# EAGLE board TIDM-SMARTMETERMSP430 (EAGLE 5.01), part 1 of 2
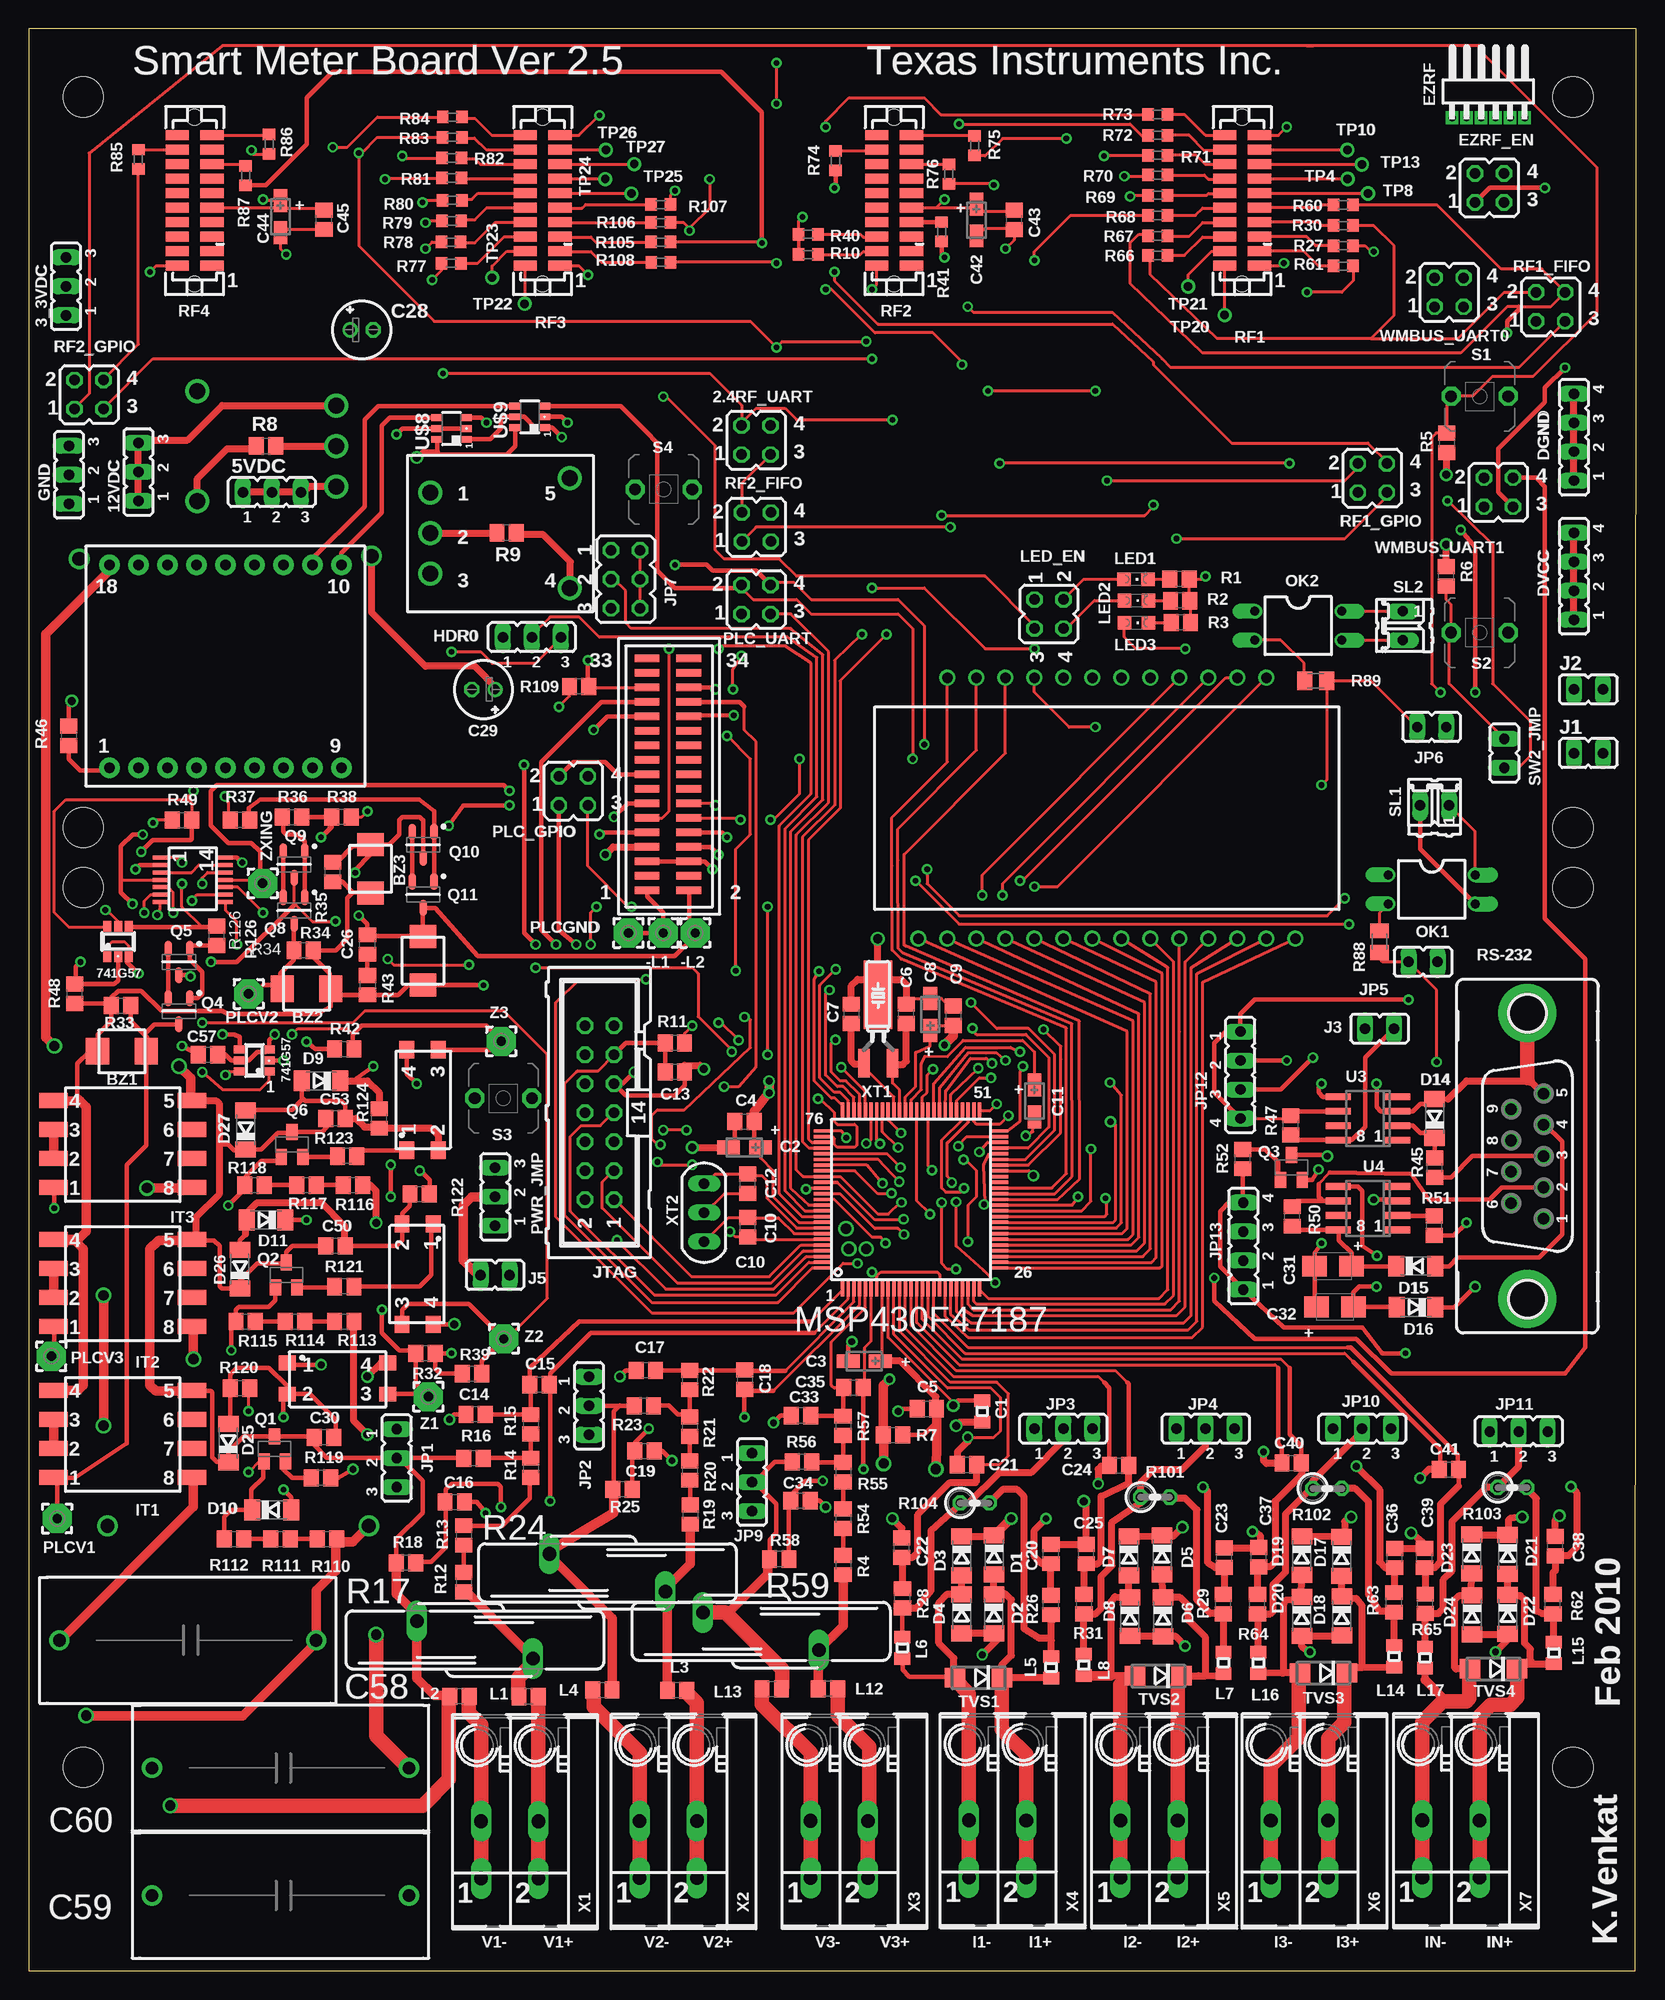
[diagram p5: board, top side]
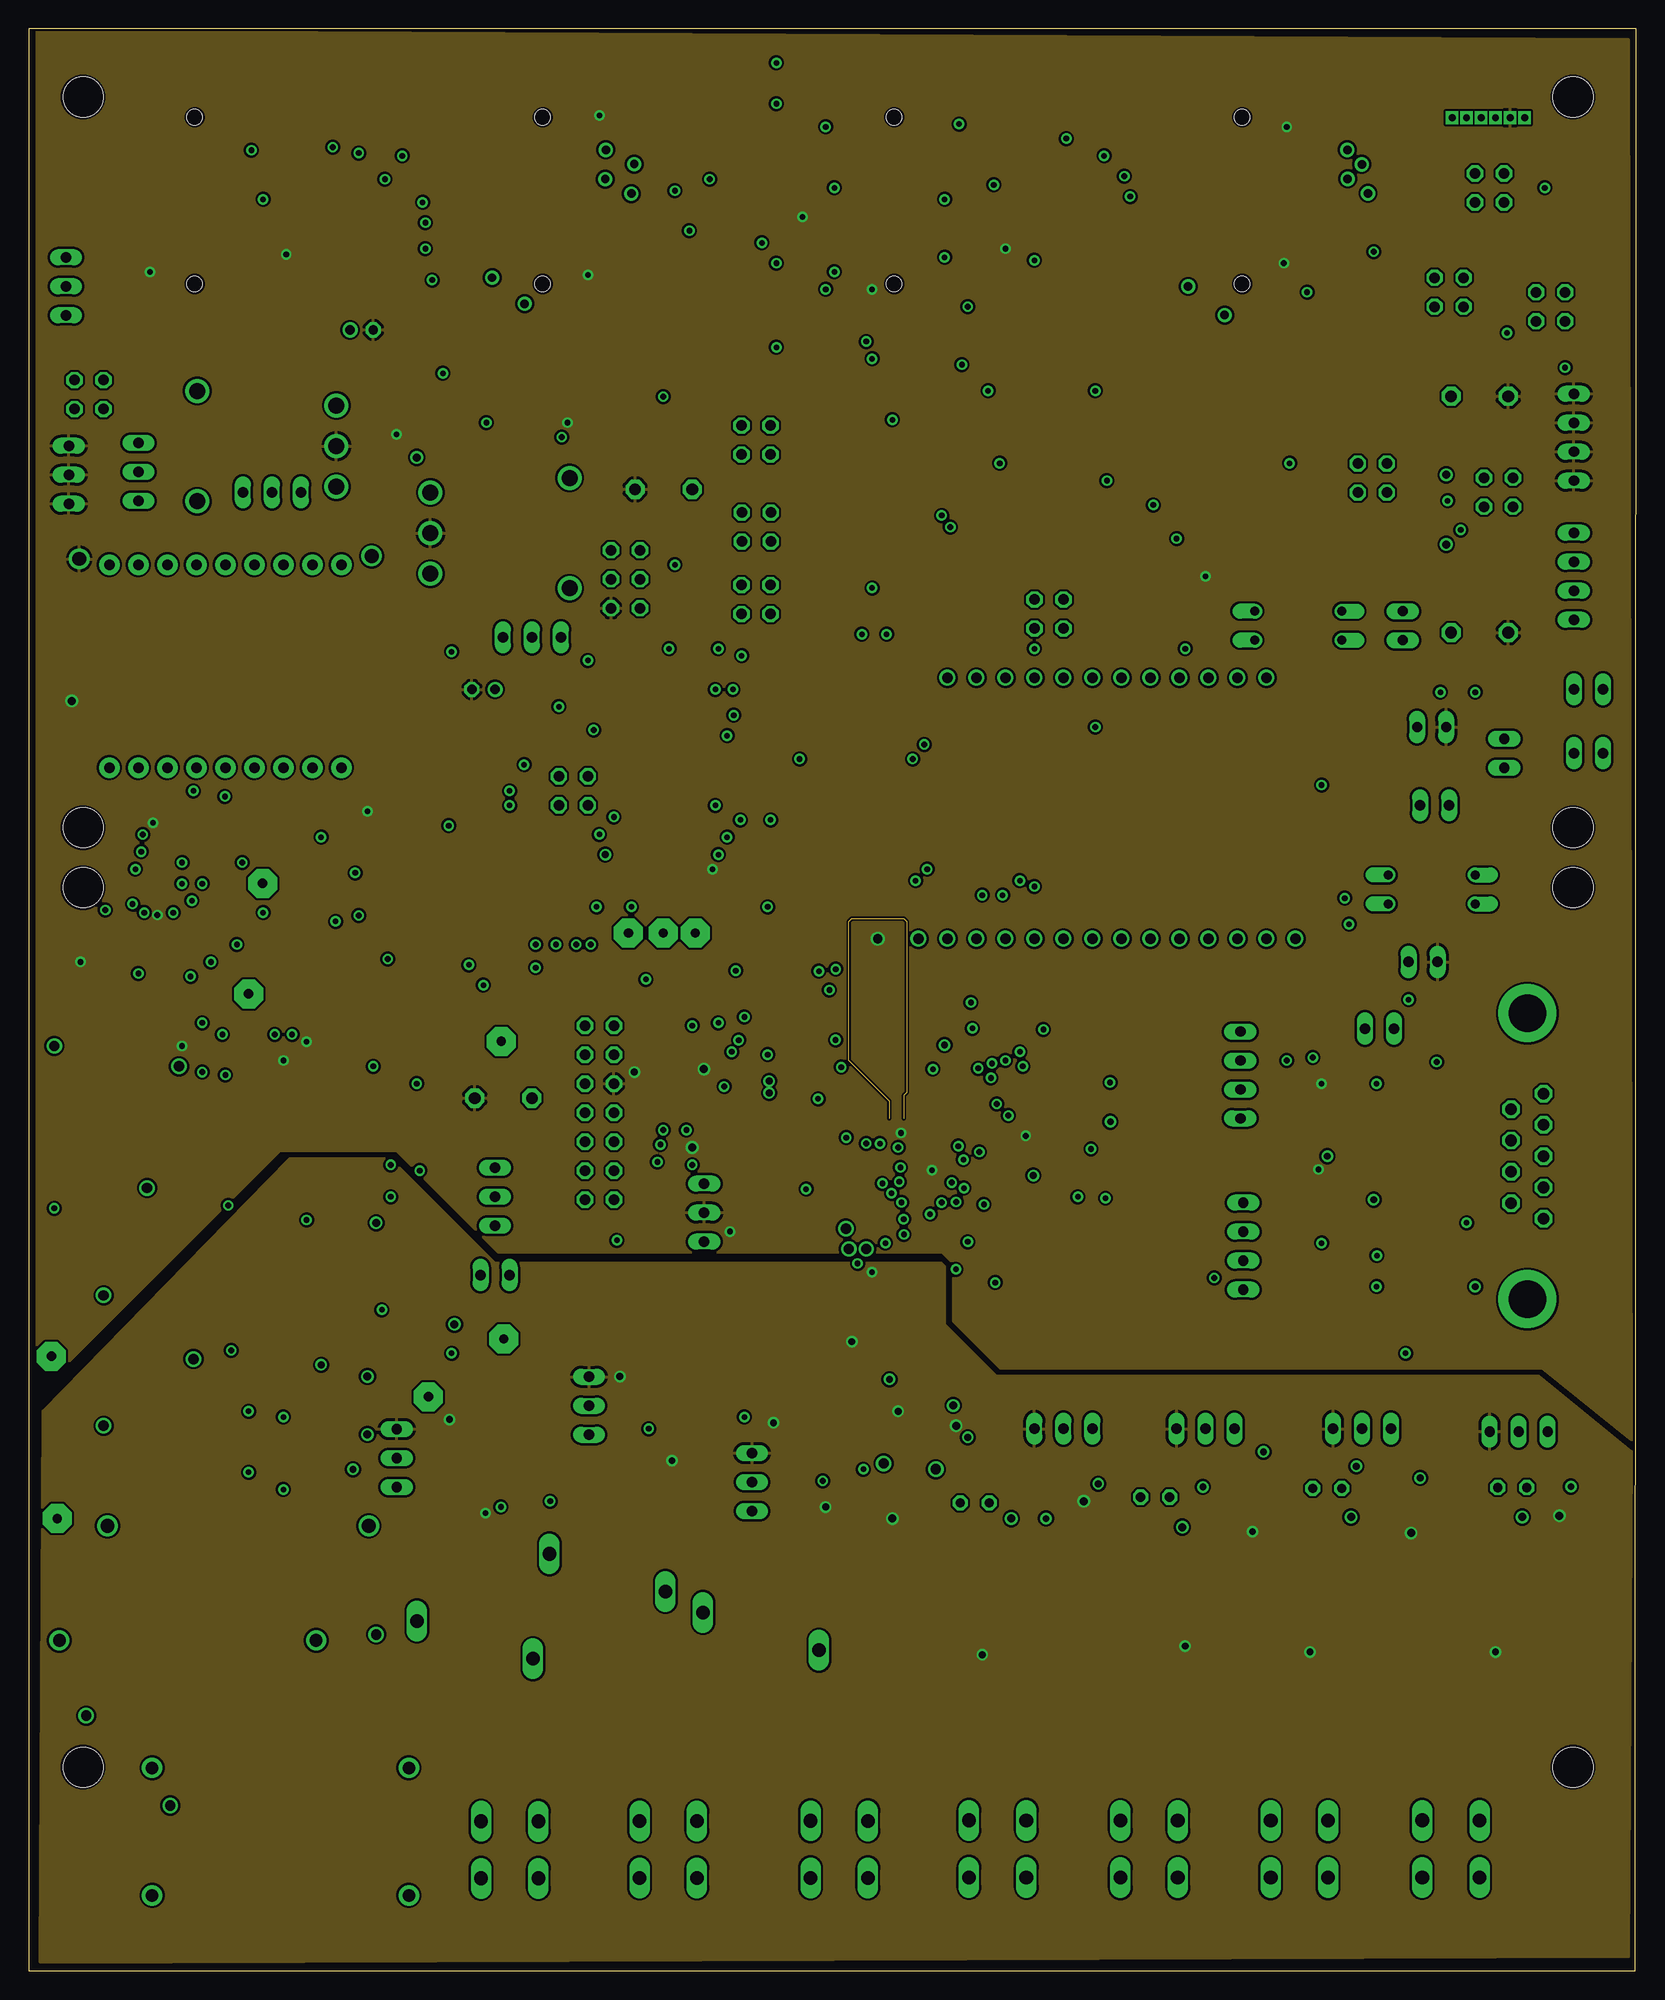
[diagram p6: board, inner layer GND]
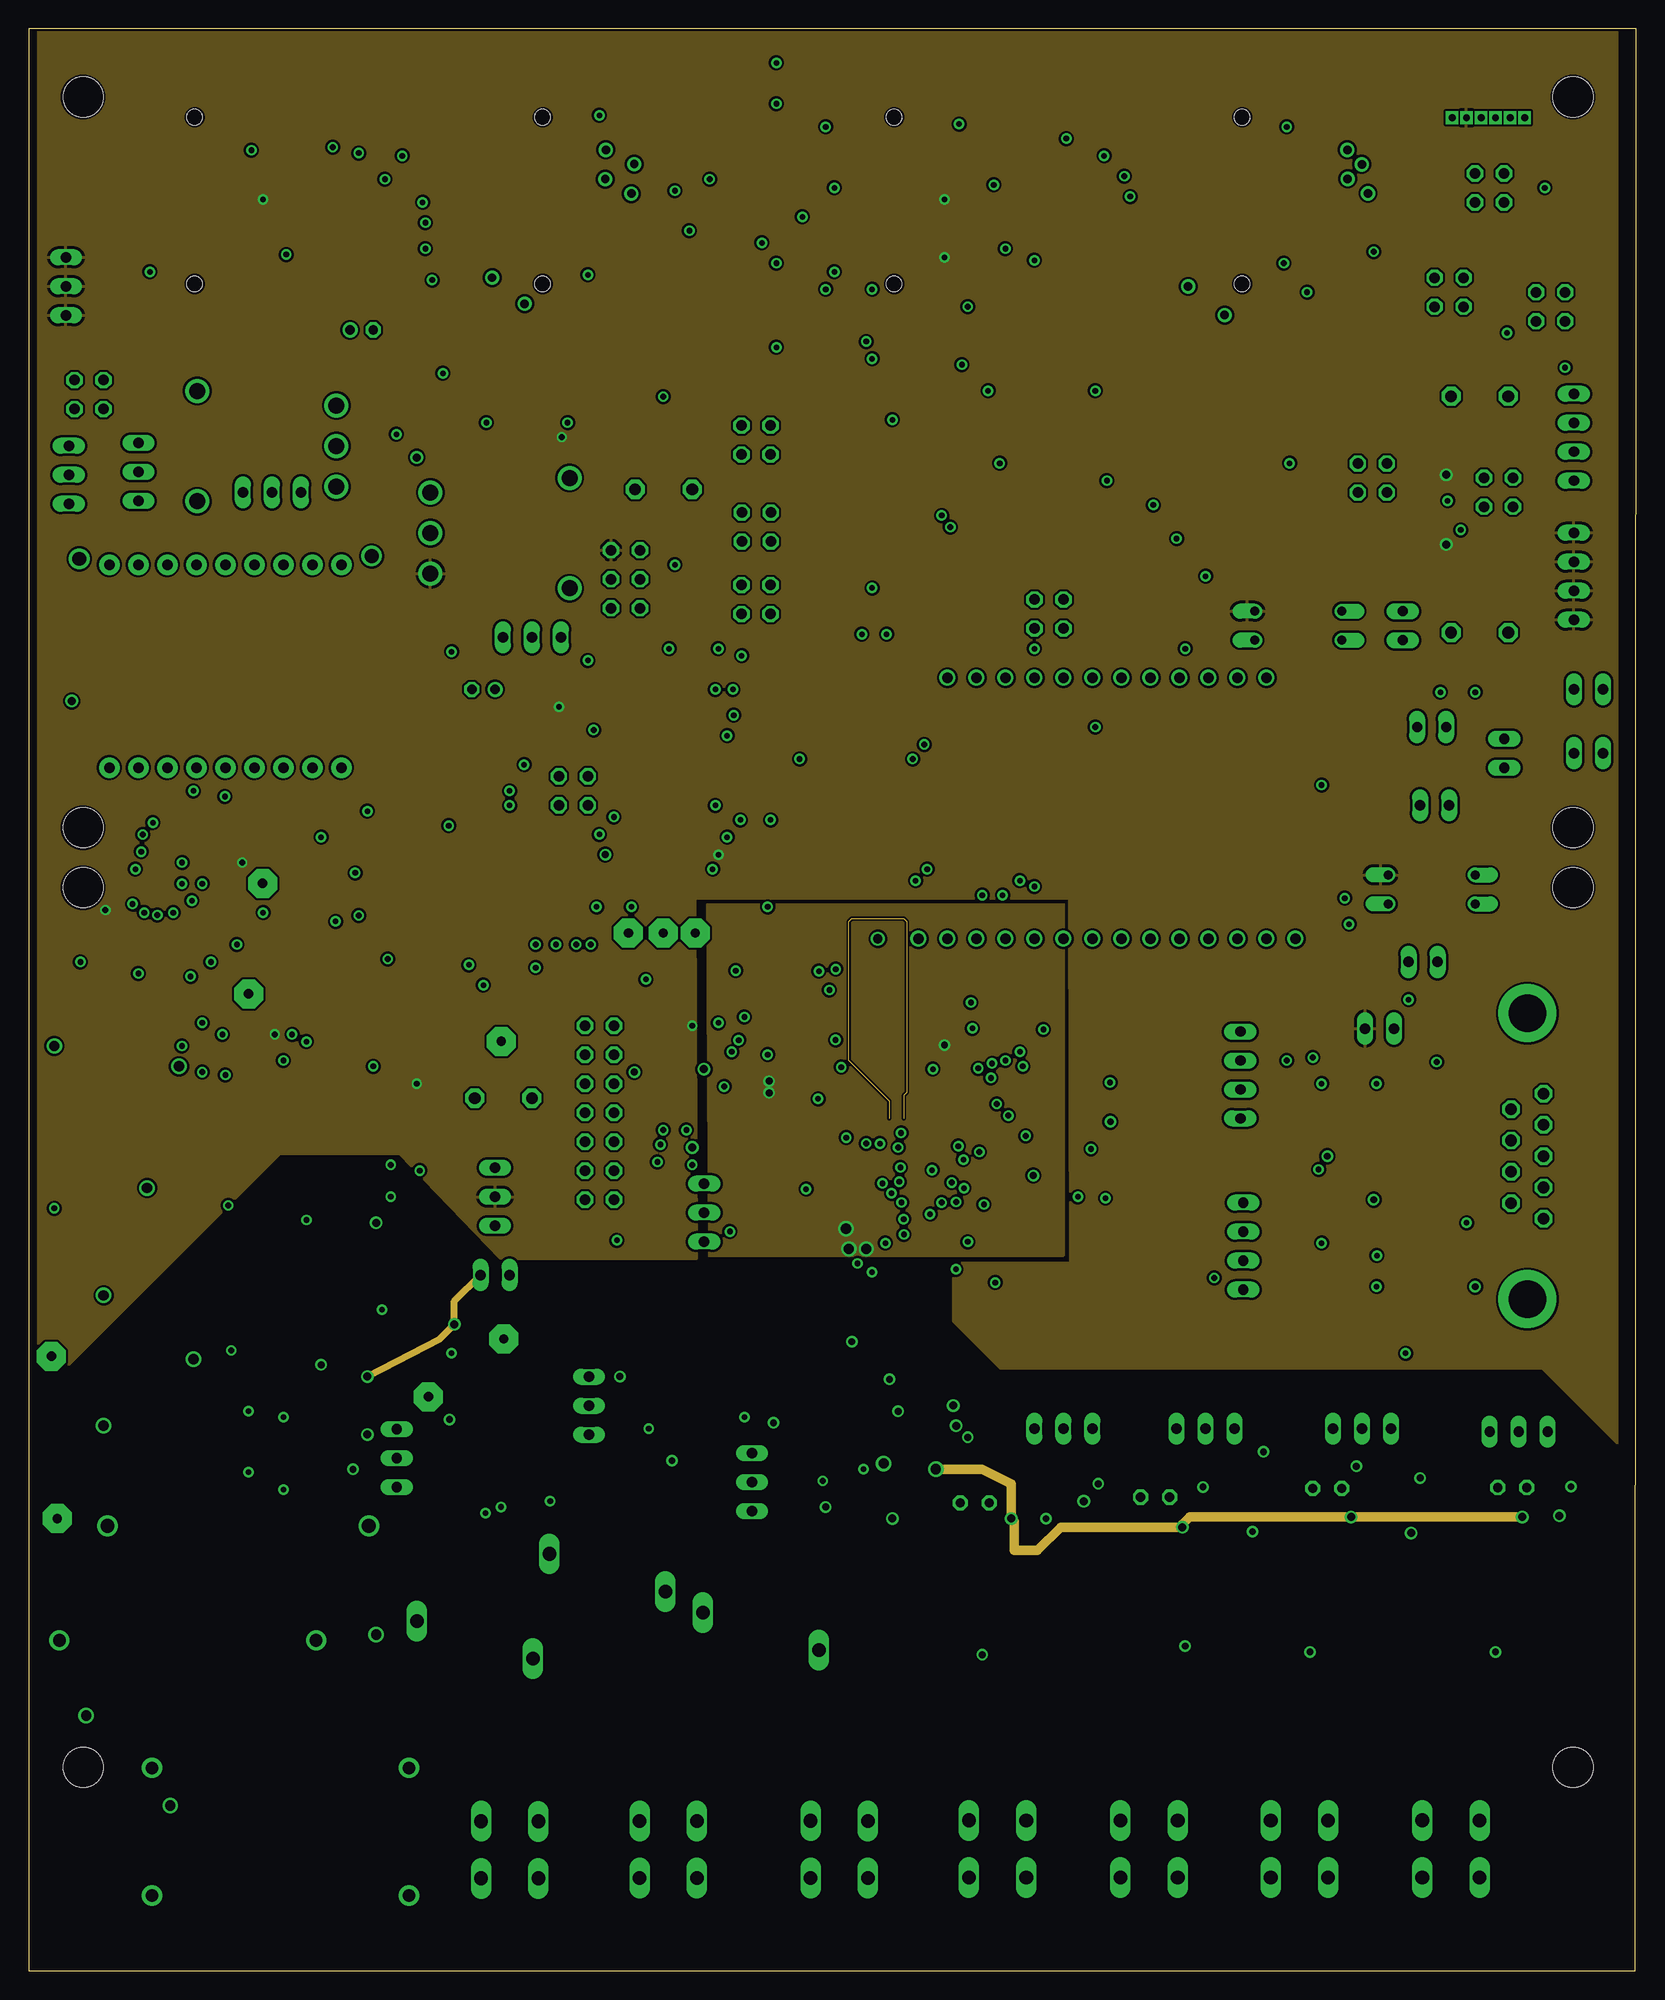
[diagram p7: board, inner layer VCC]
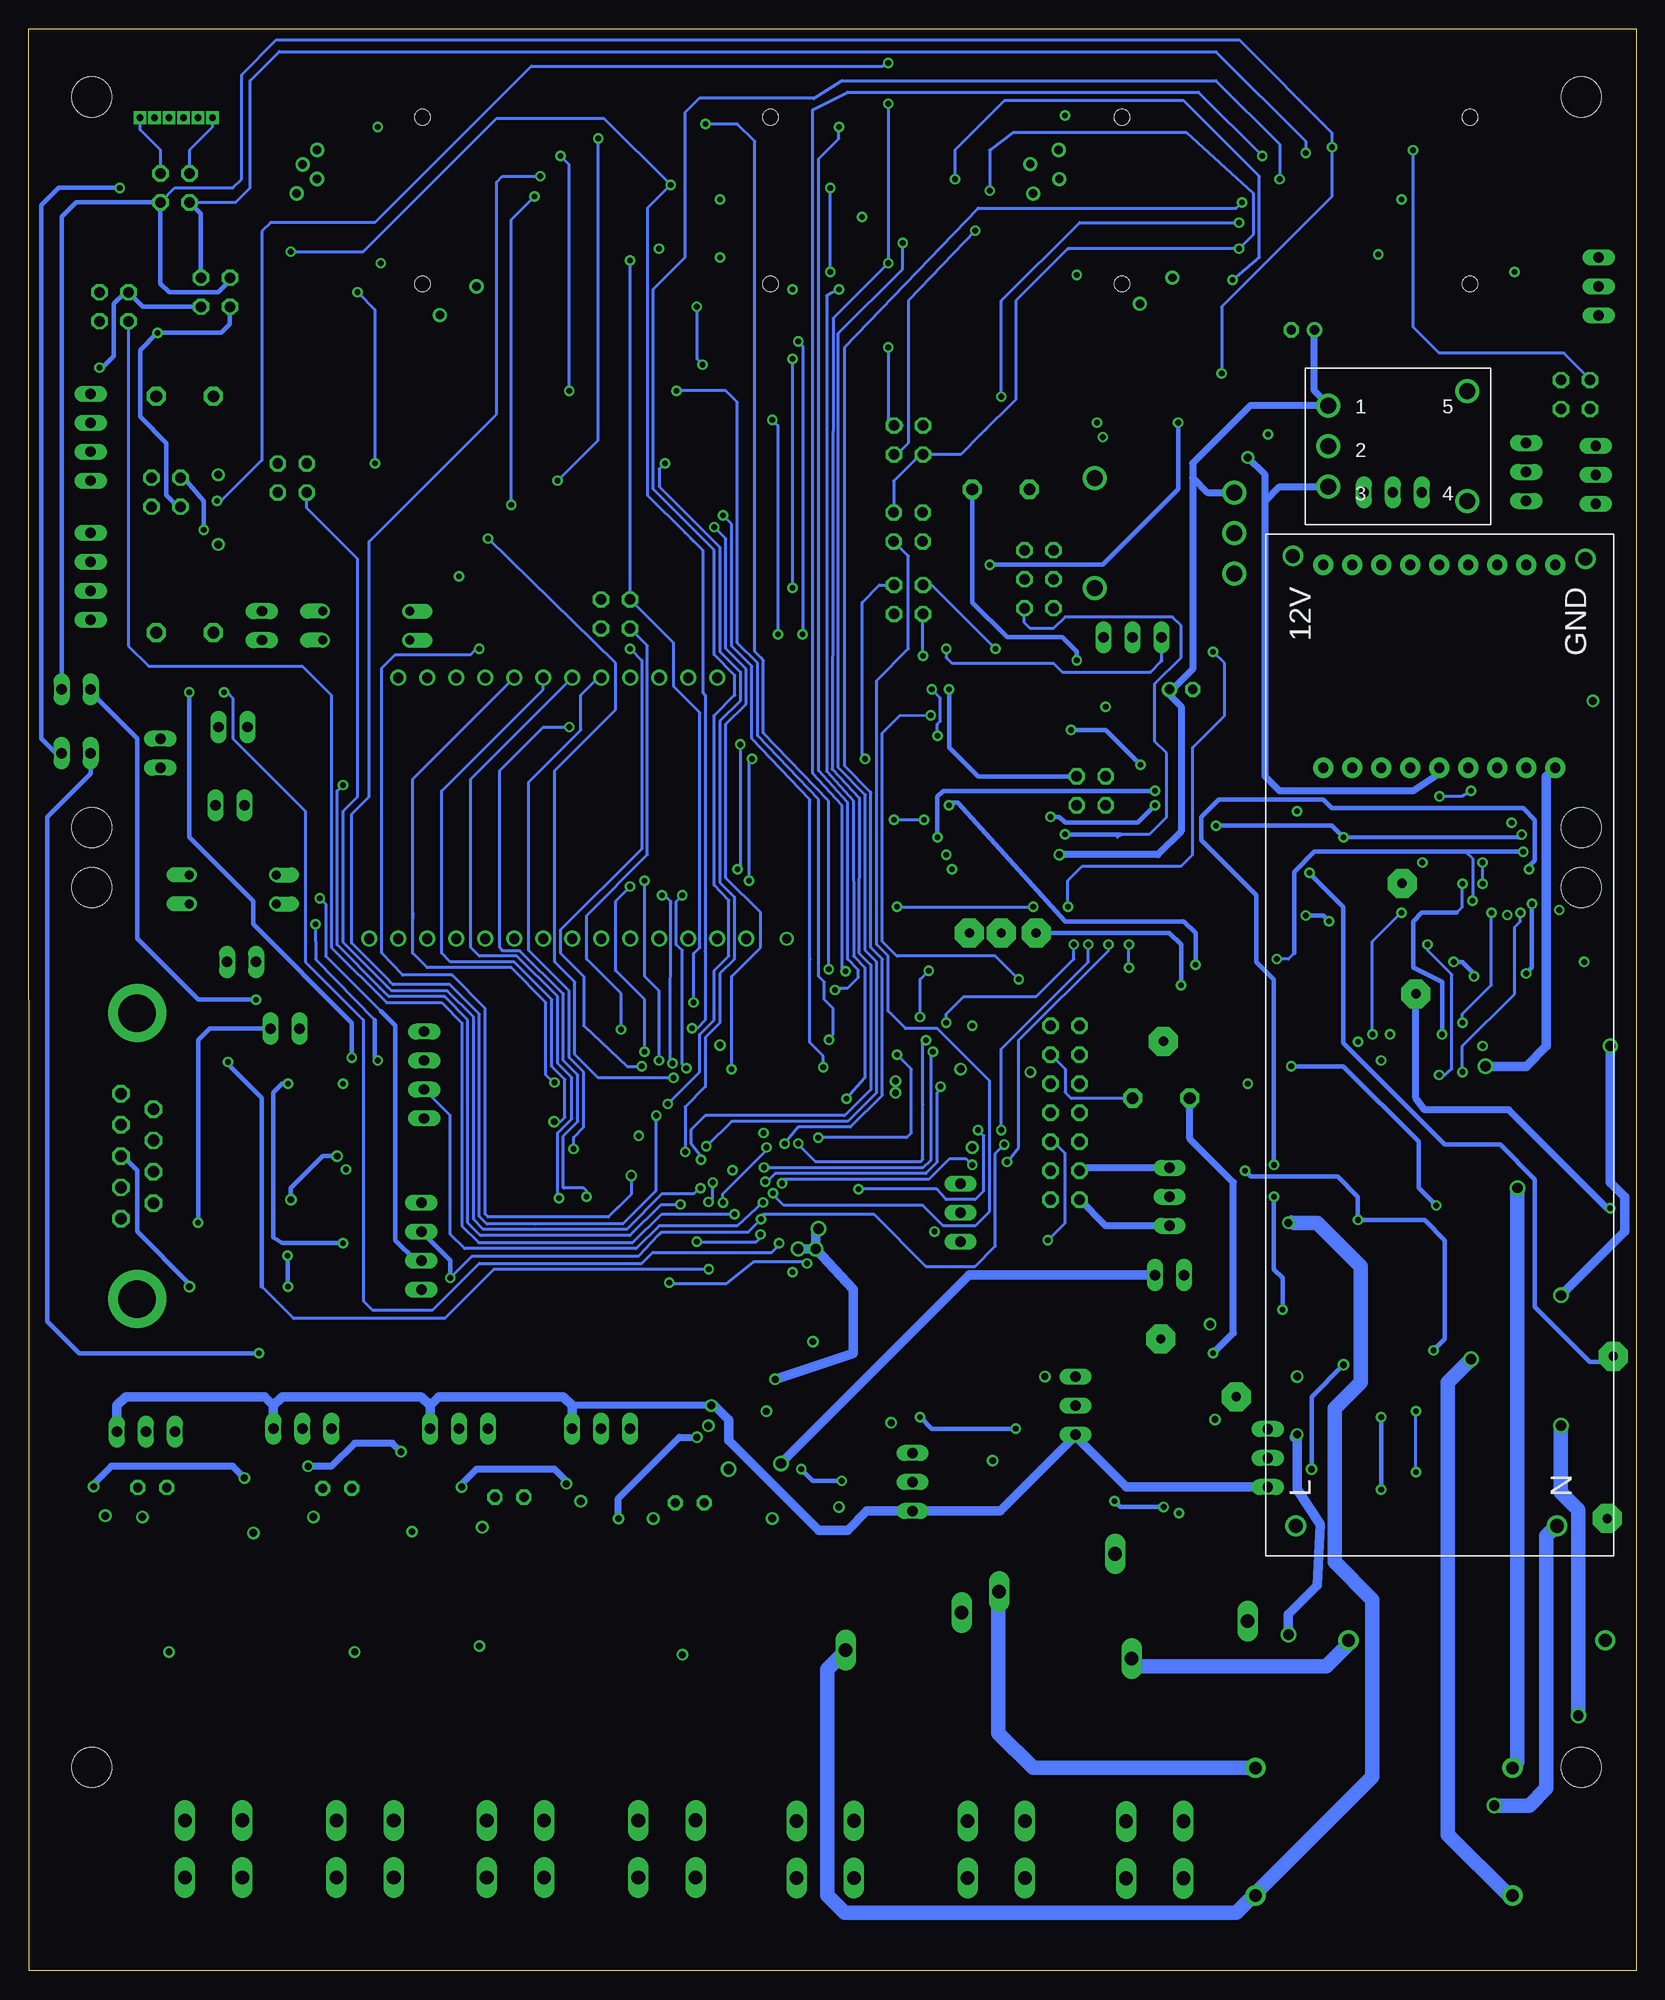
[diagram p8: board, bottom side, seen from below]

Size 140.8 x 170.18 mm. Coordinates in mm from the lower left corner, seen from the top.
Outline: 0,0 140.75,0 140.8,170.18 0,170.18 0,0
Copper layers (1*2*15*16): Top 0.035mm / dielectric 1.5mm / GND 0.035mm / dielectric 1.5mm / VCC 0.035mm / dielectric 1.5mm / Bottom 0.035mm
Design rules "MSP430 PCBExpress ZA 06 *": minimum track width 8mil, minimum drill 14mil, track to track 8mil, track to pad 8mil, pad to pad 7mil, via to via 10mil, smd to smd 8mil, copper to edge 8mil, drill to drill 8mil, minimum pad ring 10mil, minimum via ring 8mil, stop-mask expansion 8mil, vias tented up to drill 15mil, thermal gap 10mil
Holes 3.5 mm at 4.78,100.16 4.78,94.91 4.78,17.85 135.28,164.18 135.28,100.16 135.28,94.91 135.28,17.85 4.78,164.18

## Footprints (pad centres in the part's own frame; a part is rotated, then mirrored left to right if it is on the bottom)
JP2Q = drill 0.914 octagon: 1 -1.27,-1.27; 2 -1.27,1.27; 3 1.27,-1.27; 4 1.27,1.27
JP2 = drill 0.914 long: 1 -2.54,0; 2 0,0; 3 2.54,0
SOT23-6 = smd 0.69 x 0.99: 1 -0.95,-1.29; 2 0,-1.29; 3 0.95,-1.29; 4 0.95,1.3; 5 0.006,1.3; 6 -0.95,1.3
2,54/0,8 = drill 0.813 pad 2.54 octagon: 1 0,0
SOD15 = smd 2.028 x 2.3: P$1 -2.24,0.03; P$2 2.03,0.03
0805 = smd 1.092 x 1.397: 1 -0.94,0; 2 0.94,0
CT3216 = smd 2 x 1.2: + -1.4,0; - 1.4,0
C0805 = smd 1.3 x 1.5: 1 -0.85,0; 2 0.85,0
E2-5 = drill 0.813 pad 1.27 round: + -1.016,0 | drill 0.813 pad 1.27 octagon: - 1.016,0
B/3528-21W = smd 2.15 x 1.8: + 1.625,0; - -1.625,0
C17 = drill 1.1 pad 1.778 round: 1 -11.5,0; 2 11,0
SOD80C = smd 1.4 x 1.8: A 1.7,0; C -1.7,0
SOD80C@1 = smd 1.4 x 1.8: A 1.7,0; C -1.7,0
JP4 = drill 0.914 long: 1 -3.81,0; 2 -1.27,0; 3 1.27,0; 4 3.81,0
SL127L6_MPE = drill 0.6 pad 0.889 square: 1 -3.17,0.07; 2 -1.91,0.07; 3 -0.63,0.07; 4 0.63,0.07; 5 1.91,0.07; 6 3.18,0.07
OPTOCOUPLER_FOD = smd 1.5 x 1.3: 1 -4.48,1.45; 2 -4.48,-1.29; 3 4.32,-1.29; 4 4.32,1.45
JP1 = drill 0.914 long: 1 0,-1.27; 2 0,1.27
JP3Q = drill 0.914 octagon: 1 -2.54,-1.27; 2 -2.54,1.27; 3 0,-1.27; 4 0,1.27; 5 2.54,-1.27; 6 2.54,1.27
ML14 = drill 0.914 octagon: 1 -7.62,-1.27; 2 -7.62,1.27; 3 -5.08,-1.27; 4 -5.08,1.27; 5 -2.54,-1.27; 6 -2.54,1.27; 7 0,-1.27; 8 0,1.27; 9 2.54,-1.27; 10 2.54,1.27; 11 5.08,-1.27; 12 5.08,1.27; 13 7.62,-1.27; 14 7.62,1.27
R0805 = smd 1.3 x 1.5: 1 -0.85,0; 2 0.85,0
SBLCDA4 = drill 0.889 round: P$1 3.81,-20.32; P$2 6.35,-20.32; P$3 8.89,-20.32; P$4 11.43,-20.32; P$5 13.97,-20.32; P$6 16.51,-20.32; P$7 19.05,-20.32; P$8 21.59,-20.32; P$9 24.13,-20.32; P$10 26.67,-20.32; P$11 29.21,-20.32; P$12 31.75,-20.32; P$13 34.29,-20.32; P$14 36.83,-20.32; P$15 34.29,2.54; P$16 31.75,2.54; P$17 29.21,2.54; P$18 26.67,2.54; P$19 24.13,2.54; P$20 21.59,2.54; P$21 19.05,2.54; P$22 16.51,2.54; P$23 13.97,2.54; P$24 11.43,2.54; P$25 8.89,2.54; P$26 6.35,2.54
CHIPLED_0805 = smd 1.2 x 1.2: A 0,-1.05; C 0,1.05
PZ100 = smd 1.4 x 0.3: 1 -7.78,5.38; 2 -7.78,4.88; 3 -7.78,4.38; 4 -7.78,3.88; 5 -7.78,3.38; 6 -7.78,2.88; 7 -7.78,2.38; 8 -7.78,1.88; 9 -7.78,1.38; 10 -7.78,0.88; 11 -7.78,0.38; 12 -7.78,-0.12; 13 -7.78,-0.62; 14 -7.78,-1.12; 15 -7.78,-1.62; 16 -7.78,-2.12; 17 -7.78,-2.62; 18 -7.78,-3.12; 19 -7.78,-3.62; 20 -7.78,-4.12; 21 -7.78,-4.62; 22 -7.78,-5.12; 23 -7.78,-5.62; 24 -7.78,-6.12; 25 -7.78,-6.62; 51 7.82,-6.62; 52 7.82,-6.12; 53 7.82,-5.62; 54 7.82,-5.12; 55 7.82,-4.62; 56 7.82,-4.12; 57 7.82,-3.62; 58 7.82,-3.12; 59 7.82,-2.62; 60 7.82,-2.12; 61 7.82,-1.62; 62 7.82,-1.12; 63 7.82,-0.62; 64 7.82,-0.12; 65 7.82,0.38; 66 7.82,0.88; 67 7.82,1.38; 68 7.82,1.88; 69 7.82,2.38; 70 7.82,2.88; 71 7.82,3.38; 72 7.82,3.88; 73 7.82,4.38; 74 7.82,4.88; 75 7.82,5.38 | smd 0.3 x 1.4: 26 -5.98,-8.42; 27 -5.48,-8.42; 28 -4.98,-8.42; 29 -4.48,-8.42; 30 -3.98,-8.42; 31 -3.48,-8.42; 32 -2.98,-8.42; 33 -2.48,-8.42; 34 -1.98,-8.42; 35 -1.48,-8.42; 36 -0.98,-8.42; 37 -0.48,-8.42; 38 0.02,-8.42; 39 0.52,-8.42; 40 1.02,-8.42; 41 1.52,-8.42; 42 2.02,-8.42; 43 2.52,-8.42; 44 3.02,-8.42; 45 3.52,-8.42; 46 4.02,-8.42; 47 4.52,-8.42; 48 5.02,-8.42; 49 5.52,-8.42; 50 6.02,-8.42; 76 6.02,7.18; 77 5.52,7.18; 78 5.02,7.18; 79 4.52,7.18; 80 4.02,7.18; 81 3.52,7.18; 82 3.02,7.18; 83 2.52,7.18; 84 2.02,7.18; 85 1.52,7.18; 86 1.02,7.18; 87 0.52,7.18; 88 0.02,7.18; 89 -0.48,7.18; 90 -0.98,7.18; 91 -1.48,7.18; 92 -1.98,7.18; 93 -2.48,7.18; 94 -2.98,7.18; 95 -3.48,7.18; 96 -3.98,7.18; 97 -4.48,7.18; 98 -4.98,7.18; 99 -5.48,7.18; 100 -5.98,7.18
DIL04 = drill 0.813 offset: 1 -1.27,-3.81; 2 1.27,-3.81; 3 1.27,3.81; 4 -1.27,3.81
SOT23-BEC = smd 1 x 1.4: B -0.95,-1.1; C 0,1.1; E 0.95,-1.1
SOT23-BEC@1 = smd 1 x 1.4: B -0.95,-1.1; C 0,1.1; E 0.95,-1.1
SOT95P280X135-3N = smd 1.4 x 0.65: 1 -1.15,0.95; 2 -1.15,-0.95; 3 1.15,0
R0603 = smd 1 x 1.1: 1 -0.85,0; 2 0.85,0
S20K275 = drill 1.194 long: 1 -1.651,-5.08; 2 1.651,5.08
R0603@1 = smd 1 x 1.1: 1 -0.85,0; 2 0.85,0
M0805@1 = smd 1.3 x 1.6: 1 -0.95,0; 2 0.95,0
0207/2V = drill 0.813 octagon: 1 -1.27,0; 2 1.27,0
TFM-110-02-SM-D-A-K = smd 2.032 x 0.889: 1 -1.524,5.715; 2 1.524,5.715; 3 -1.524,4.445; 4 1.524,4.445; 5 -1.524,3.175; 6 1.524,3.175; 7 -1.524,1.905; 8 1.524,1.905; 9 -1.524,0.635; 10 1.524,0.635; 11 -1.524,-0.635; 12 1.524,-0.635; 13 -1.524,-1.905; 14 1.524,-1.905; 15 -1.524,-3.175; 16 1.524,-3.175; 17 -1.524,-4.445; 18 1.524,-4.445; 19 -1.524,-5.715; 20 1.524,-5.715 | hole 1.359: 0,7.303; 0,-7.303
F09VP = drill 1.016 octagon: 1 5.486,1.422; 2 2.743,1.422; 3 0,1.422; 4 -2.743,1.422; 5 -5.486,1.422; 6 4.115,-1.422; 7 1.372,-1.422; 8 -1.372,-1.422; 9 -4.115,-1.422 | drill 3.302 pad 5.08 round: G1 -12.522,0; G2 12.522,0
PBTH = drill 1.016 pad 1.676 octagon: 1 -0.001,0.001; 2 5.001,0.001
02P = drill 0.914 long: 1 -1.27,0; 2 1.27,0
TST_PNT = drill 0.737 round: TP 0,0
DO214AC = smd 1.8 x 1.7: A 2.05,0; C -2.05,0
SO08 = smd 0.6 x 2.2: 1 -1.905,-2.6; 2 -0.635,-2.6; 3 0.635,-2.6; 4 1.905,-2.6; 5 1.905,2.6; 6 0.635,2.6; 7 -0.635,2.6; 8 -1.905,2.6
PLC_SMB25 = smd 2.5 x 1.3: 1 6.15,3.75; 2 6.15,1.21; 3 6.15,-1.33; 4 6.15,-3.87; 5 -5.95,-3.87; 6 -5.95,-1.33; 7 -5.95,1.21; 8 -5.95,3.75
AC_DC_12V = drill 1.2 round: 12V 43.18,12.817; GND 42.926,-12.802; L -41.791,12.563; N -41.791,-10.318
PTH08080 = drill 1.4 round: 1 -6.172,3.277; 2 -6.172,-0.279; 3 -6.172,-3.835; 4 6.02,-5.105; 5 6.02,4.547
WATT_PULSE = drill 0.9 pad 1.778 round: 1 -10.16,-7.62; 2 -7.62,-7.62; 3 -5.08,-7.62; 4 -2.54,-7.62; 5 0,-7.62; 6 2.54,-7.62; 7 5.08,-7.62; 8 7.62,-7.62; 9 10.16,-7.62; 10 10.16,10.16; 11 7.62,10.16; 12 5.08,10.16; 13 2.54,10.16; 14 0,10.16; 15 -2.54,10.16; 16 -5.08,10.16; 17 -7.62,10.16; 18 -10.16,10.16
DBV_R-PDSO-G6 = smd 0.6 x 0.99: 1 -0.95,-1.29; 2 0,-1.29; 3 0.95,-1.29; 4 0.95,1.3; 5 0,1.3; 6 -0.95,1.3
74132 = smd 0.35 x 1.27: P$1 0,-0.65; P$2 0.65,-0.65; P$3 1.3,-0.65; P$4 1.95,-0.65; P$5 2.6,-0.65; P$6 3.25,-0.65; P$7 3.9,-0.65; P$8 3.9,5.08; P$9 3.25,5.1; P$10 2.6,5.1; P$11 1.95,5.1; P$12 1.3,5.1; P$13 0.65,5.1; P$14 0,5.1
CONN34 = smd 2.15 x 0.65: 1 -1.925,-9.985; 2 1.725,-9.985; 3 -1.925,-8.715; 4 1.725,-8.715; 5 -1.925,-7.444; 6 1.725,-7.444; 7 -1.925,-6.176; 8 1.725,-6.176; 9 -1.925,-4.905; 10 1.725,-4.905; 11 -1.925,-3.635; 12 1.725,-3.635; 13 -1.925,-2.364; 14 1.725,-2.364; 15 -1.925,-1.096; 16 1.725,-1.096; 17 -1.925,0.175; 18 1.725,0.175; 19 -1.925,1.445; 20 1.725,1.445; 21 -1.925,2.716; 22 1.725,2.716; 23 -1.925,3.984; 24 1.725,3.984; 25 -1.925,5.255; 26 1.725,5.255; 27 -1.925,6.525; 28\ 1.725,6.525; 29 -1.925,7.796; 30 1.725,7.796; 31 -1.925,9.064; 32 1.725,9.064; 33 -1.925,10.335; 34 1.725,10.335
FFKV2 = drill 1.194 long: 1 -3.6,-1.01; 1A -3.6,3.99; 2 1.42,-1.01; 2A 1.42,3.98
CM200T = smd 1 x 2.5: P1 -1.25,-5; P2 1.25,-5 | smd 2.5 x 6: P3 0,1
X905 = drill 0.914 long: 1 -2.54,0; 2 0,0; 3 2.54,0

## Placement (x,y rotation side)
2.4RF_UART  [JP2Q]  63.72,134.12 0 top
3_3VDC  [JP2]  3.27,147.59 90 top
5VDC  [JP2]  21.31,129.55 0 top
12VDC  [JP2]  9.62,131.33 90 top
741G57  SOT23-6  [SOT23-6]  19.78,79.77 90 top
741G157_1  SOT23-6  [SOT23-6]  7.84,90.18 0 top
-L1  [2,54/0,8]  55.6,90.94 90 top
-L2  [2,54/0,8]  58.39,90.94 90 top
BZ1  SM6TXX  [SOD15]  8.07,80.61 180 top
BZ2  SM6TXX  [SOD15]  24.46,86.02 0 top
BZ3  SM6TXX  [SOD15]  29.92,96.46 270 top
BZ4  SM6TXX  [SOD15]  34.51,88.4 270 top
C1  100n  [0805]  83.54,49.03 90 top
C2  10u  [CT3216]  62.71,72.15 180 top
C3  10u  [CT3216]  73.2,53.43 180 top
C4  0.1u  [C0805]  62.71,74.43 0 top
C5  0.1u  [C0805]  78.68,49.26 0 top
C6  12pF  [C0805]  76.88,83.85 90 top
C7  12pF  [C0805]  72.07,83.85 270 top
C8  10u  [CT3216]  78.99,83.81 90 top
C9  0.1u  [C0805]  81,83.68 270 top
C10  12pF  [C0805]  62.99,65.16 90 top
C11  10u  [CT3216]  88.11,76.21 270 top
C12  12pF  [C0805]  62.99,68.97 90 top
C13  0.1u  [C0805]  56.61,78.75 180 top
C14  47p  [C0805]  39.16,48.76 180 top
C15  15n  [C0805]  44.75,51.37 0 top
C16  47p  [C0805]  37.33,41.11 0 top
C17  47p  [C0805]  54.07,52.62 180 top
C18  15n  [C0805]  62.73,51.8 270 top
C19  47p  [C0805]  53.94,45.58 0 top
C20  47p  [C0805]  89.56,36.54 90 top
C21  15n  [C0805]  82.19,44.36 0 top
C22  47p  [C0805]  76.5,37.1 90 top
C23  47p  [C0805]  104.74,36.21 90 top
C24  15n  [C0805]  95.52,44.31 0 top
C25  47p  [C0805]  92.65,36.54 90 top
C26  0.047u  [C0805]  29.69,89.93 90 top
C28  220uF  [E2-5]  29.18,143.78 0 top
C29  220uF  [E2-5]  39.85,112.28 180 top
C30  0.33uF  [C0805]  25.88,46.75 180 top
C31  10uF  [B/3528-21W]  114.27,61.73 0 top
C32  10uF  [B/3528-21W]  114.45,58.18 180 top
C33  47p  [C0805]  67.66,48.65 180 top
C34  47p  [C0805]  67.61,41.21 0 top
C35  15n  [C0805]  72.26,51.12 0 top
C36  47p  [C0805]  119.68,36.18 90 top
C37  47p  [C0805]  107.74,36.26 90 top
C38  47p  [C0805]  133.73,37.22 90 top
C39  47p  [C0805]  122.27,36.18 90 top
C40  15n  [C0805]  110.64,44.51 0 top
C41  15n  [C0805]  124.4,43.95 0 top
C42  10u  [CT3216]  83.03,153.4 270 top
C43  0.1u  [C0805]  86.33,153.4 90 top
C44  10u  [CT3216]  22.07,153.68 270 top
C45  0.1u  [C0805]  25.88,153.43 90 top
C50  0.33uF  [C0805]  26.89,63.51 180 top
C53  0.33uF  [C0805]  26.89,74.69 180 top
C57  0.1u  [C0805]  15.72,80.28 0 top
C58  0.47u  [C17]  14.19,28.97 0 top
C59  0.47u  [C17]  22.32,6.62 0 top
C60  0.47u  [C17]  22.32,17.79 0 top
D1  PMLL4148  [SOD80C]  84.58,36.46 270 top
D2  PMLL4148  [SOD80C]  84.55,31.28 270 top
D3  PMLL4148  [SOD80C]  81.73,36.36 270 top
D4  PMLL4148  [SOD80C]  81.73,31.28 270 top
D5  PMLL4148  [SOD80C]  99.28,36.46 270 top
D6  PMLL4148  [SOD80C]  99.36,31.03 270 top
D7  PMLL4148  [SOD80C]  96.39,36.36 270 top
D8  PMLL4148  [SOD80C]  96.46,31.05 270 top
D9  PMLL4148  [SOD80C]  25.62,77.99 180 top
D10  PMLL4148  [SOD80C]  21.31,40.4 0 top
D11  PMLL4148  [SOD80C]  20.8,65.8 180 top
D14  1N4148  [SOD80C]  123.16,74.69 90 top
D15  1N4148  [SOD80C]  121.51,61.76 0 top
D16  1N4148  [SOD80C]  121.53,58.15 180 top
D17  PMLL4148  [SOD80C]  115.01,36.33 270 top
D18  PMLL4148  [SOD80C]  115.03,31.1 270 top
D19  PMLL4148  [SOD80C]  111.53,36.39 270 top
D20  PMLL4148  [SOD80C]  111.53,31.08 270 top
D21  PMLL4148  [SOD80C]  129.56,36.51 270 top
D22  PMLL4148  [SOD80C]  129.56,31.25 270 top
D23  PMLL4148  [SOD80C]  126.41,36.54 270 top
D24  PMLL4148  [SOD80C]  126.44,31.2 270 top
D25  [SOD80C@1]  17.5,46.24 90 top
D26  [SOD80C@1]  18.51,61.48 90 top
D27  [SOD80C@1]  19.02,73.67 90 top
DGND  GND_JMP  [JP4]  135.35,134.38 90 top
DVCC  [JP4]  135.35,122.19 90 top
EZRF  SL127L6TH  [SL127L6_MPE]  127.86,162.29 0 top
EZRF_EN  [JP2Q]  127.96,156.22 0 top
GND  [JP2]  3.53,131.08 90 top
HDR0  [JP2]  44.09,116.85 0 top
IS02  OPTO_PLC  [OPTOCOUPLER_FOD]  34.01,60.97 270 top
ISO1  OPTO_PLC  [OPTOCOUPLER_FOD]  27.15,51.83 0 top
ISO3  OPTO_PLC  [OPTOCOUPLER_FOD]  34.58,76.39 90 top
J1  [JP1]  136.62,106.69 270 top
J2  [JP1]  136.62,112.28 270 top
J3  [JP1]  118.33,82.56 90 top
J5  J5  [JP1]  40.86,60.97 270 top
JP1  JP1  [JP2]  32.25,44.95 270 top
JP2  JP2  [JP2]  49.09,49.52 270 top
JP3  JP3  [JP2]  90.65,47.51 0 top
JP4  JP4  [JP2]  103.09,47.51 0 top
JP5  [JP1]  122.14,88.4 270 top
JP6  [JP1]  122.91,108.98 270 top
JP7  [JP3Q]  52.29,121.93 270 top
JP9  JP9  [JP2]  63.37,42.84 270 top
JP10  JP10  [JP2]  116.81,47.51 0 top
JP11  JP11  [JP2]  130.53,47.26 0 top
JP12  [JP4]  106.14,78.5 270 top
JP13  [JP4]  106.4,63.51 90 top
JTAG  MSP430 JTAG  [ML14]  50.01,75.2 90 top
L1  EXCML20A  [R0805]  43.81,24.04 180 top
L2  EXCML20A  [R0805]  37.74,24.07 180 top
L3  EXCML20A  [R0805]  56.81,24.6 180 top
L4  EXCML20A  [R0805]  50.26,24.63 0 top
L5  BLM21BD121SN1D  [0805]  89.57,26.61 90 top
L6  BLM21BD121SN1D  [0805]  76.53,28.32 90 top
L7  BLM21BD121SN1D  [0805]  104.67,27.01 90 top
L8  BLM21BD121SN1D  [0805]  92.43,26.81 90 top
L12  EXCML20A  [R0805]  70.02,24.73 180 top
L13  EXCML20A  [R0805]  65.1,24.73 0 top
L14  BLM21BD121SN1D  [0805]  119.62,27.58 90 top
L15  BLM21BD121SN1D  [0805]  133.6,27.87 90 top
L16  BLM21BD121SN1D  [0805]  107.72,27 90 top
L17  BLM21BD121SN1D  [0805]  122.32,27.46 90 top
LCD1  SBLCDA4  [SBLCDA4]  74.14,110.76 0 top
LED1  [CHIPLED_0805]  97,121.93 270 top
LED2  [CHIPLED_0805]  97.05,120.06 270 top
LED3  [CHIPLED_0805]  97.05,118.11 270 top
LED_EN  [JP2Q]  89.38,118.88 270 top
MSP430F47187  MSP430F471X7PZ100  [PZ100]  76.68,67.58 90 top
OK1  TIL191  [DIL04]  122.91,94.75 270 top
OK2  TIL191  [DIL04]  111.22,117.87 270 top
PLC_GPIO  [JP2Q]  47.72,103.39 0 top
PLC_UART  [JP2Q]  63.72,120.15 0 top
PLCGND  [2,54/0,8]  52.55,90.94 90 top
PLCV1  [2,54/0,8]  2.51,39.64 180 top
PLCV2  [2,54/0,8]  19.27,85.61 90 top
PLCV3  [2,54/0,8]  2,53.86 270 top
PWR_JMP  [JP2]  40.86,67.83 90 top
Q1  BC817-40LT1SMD  [SOT23-BEC]  21.56,45.73 0 top
Q2  BC817-40LT1SMD  [SOT23-BEC]  22.58,60.97 0 top
Q3  BC807SMD  [SOT23-BEC@1]  110.61,70.4 0 top
Q4  MOSFET-NCH_SOT-23  [SOT95P280X135-3N]  13.18,84.09 270 top
Q5  MOSFET-NCH_SOT-23  [SOT95P280X135-3N]  13.18,88.4 270 top
Q6  BC817-40LT1SMD  [SOT23-BEC]  23.08,72.4 0 top
Q8  MOSFET-NCH_SOT-23  [SOT95P280X135-3N]  23.26,92.9 270 top
Q9  MOSFET-NCH_SOT-23  [SOT95P280X135-3N]  23.26,96.94 270 top
Q10  MOSFET-NCH_SOT-23  [SOT95P280X135-3N]  34.56,98.67 270 top
Q11  MOSFET-NCH_SOT-23  [SOT95P280X135-3N]  34.56,94.3 270 top
R1  560  [R0805]  100.81,121.93 180 top
R2  560  [R0805]  100.87,120.04 180 top
R3  560  [R0805]  100.93,118.12 180 top
R4  330k  [R0805]  71.34,35.57 270 top
R5  100K  [R0805]  124.23,133.87 270 top
R6  100K  [R0805]  124.18,122.19 90 top
R7  10R  [R0805]  75.71,46.95 0 top
R8  353R  [R0805]  20.8,133.62 0 top
R9  1.89K  [R0805]  41.88,126 180 top
R10  0  [R0603]  68.3,150.38 0 top
R11  47K  [R0805]  56.61,81.29 180 top
R12  330k  [R0805]  38.12,34.07 270 top
R13  330k  [R0805]  38.12,38.16 270 top
R14  330k  [R0805]  43.99,44.08 270 top
R15  1k  [R0805]  43.99,47.89 270 top
R16  1k5  [R0805]  38.98,44.92 180 top
R17  S20K275  [S20K275]  39.1,29.01 270 top
R18  1k  [R0805]  33.07,35.75 180 top
R19  330k  [R0805]  57.96,39.99 270 top
R20  330k  [R0805]  57.91,43.85 270 top
R21  330k  [R0805]  57.91,47.69 270 top
R22  1k  [R0805]  57.91,51.78 270 top
R23  1k5  [R0805]  53.89,49.52 180 top
R24  S20K275  [S20K275]  50.71,34.89 270 top
R25  1k  [R0805]  52.01,42.2 180 top
R26  1k  [R0805]  89.56,32.07 90 top
R27  0  [R0603@1]  115.16,151.14 180 top
R28  1k  [R0805]  76.55,32.65 90 top
R29  1k  [R0805]  104.64,32.14 90 top
R30  0  [R0603@1]  115.16,152.92 180 top
R31  1k  [R0805]  92.45,32.14 90 top
R32  1.5K  [R0805]  34.77,54.11 180 top
R33  100  [R0805]  8.1,84.59 0 top
R34  100  [R0805]  24.1,89.42 180 top
R35  100  [R0805]  26.64,96.28 90 top
R36  100K  [R0805]  23.08,101.1 0 top
R37  100K  [R0805]  18.51,100.85 180 top
R38  10K  [R0805]  27.4,101.1 180 top
R39  1.5K  [R0805]  38.83,52.34 0 top
R40  0  [R0603]  68.3,152.16 0 top
R41  0  [R0603]  79.98,152.36 270 top
R42  1.5K  [R0805]  27.66,80.78 0 top
R43  20  [R0805]  29.69,86.37 270 top
R45  1k  [R0805]  123.16,70.37 90 top
R46  0R  [R0805]  3.53,108.22 270 top
R47  2k2  [R0805]  110.56,74.08 90 top
R48  0Ohm  [R0805]  4.03,85.61 90 top
R49  10K  [R0805]  13.43,100.85 0 top
R50  2k2  [R0805]  110.69,66.1 90 top
R51  100  [R0805]  123.13,65.29 90 top
R52  2k2  [R0805]  106.34,71.13 90 top
R54  330k  [R0805]  71.34,39.64 270 top
R55  330k  [R0805]  71.34,43.7 270 top
R56  1k5  [R0805]  67.74,44.59 180 top
R57  1k  [R0805]  71.34,47.76 270 top
R58  1k  [R0805]  65.76,36.08 180 top
R59  S20K275  [S20K275]  64.16,29.75 270 top
R60  0  [R0603@1]  115.16,154.72 180 top
R61  0  [R0603@1]  115.16,149.36 180 top
R62  1k  [R0805]  133.52,32.14 90 top
R63  1k  [R0805]  119.6,32.3 90 top
R64  1k  [R0805]  107.64,32.14 90 top
R65  1k  [R0805]  122.35,32.17 90 top
R66  0  [R0603@1]  98.9,150.3 180 top
R67  0  [R0603@1]  98.9,152.01 180 top
R68  0  [R0603@1]  98.9,153.81 180 top
R69  0  [R0603@1]  98.9,155.56 180 top
R70  0  [R0603@1]  98.9,157.34 180 top
R71  0  [R0603@1]  98.9,159.07 180 top
R72  0  [R0603@1]  98.9,160.82 180 top
R73  0  [R0603@1]  98.9,162.65 180 top
R74  0  [R0603@1]  70.68,158.61 90 top
R75  0  [R0603@1]  82.88,159.91 270 top
R76  0  [R0603@1]  80.61,157.42 270 top
R77  0  [R0603@1]  37.03,149.62 180 top
R78  0  [R0603@1]  37,151.47 180 top
R79  0  [R0603@1]  37.05,153.33 180 top
R80  0  [R0603@1]  37.1,155.13 180 top
R81  0  [R0603@1]  37.08,157.09 180 top
R82  0  [R0603@1]  37.08,158.84 180 top
R83  0  [R0603@1]  37.1,160.64 180 top
R84  0  [R0603@1]  37.13,162.42 180 top
R85  0  [R0603@1]  9.62,158.71 90 top
R86  0  [R0603@1]  21.08,160.03 270 top
R87  0  [R0603@1]  19.02,157.29 270 top
R88  1k  [M0805@1]  118.33,90.18 90 top
R89  1k  [M0805@1]  112.75,113.04 180 top
R101  TBD  [0207/2V]  98.67,41.52 0 top
R102  TBD  [0207/2V]  113.76,42.28 0 top
R103  TBD  [0207/2V]  129.97,42.35 0 top
R104  TBD  [0207/2V]  82.88,41.01 0 top
R105  0  [R0603@1]  55.37,151.47 180 top
R106  0  [R0603@1]  55.37,153.17 180 top
R107  0  [R0603@1]  55.37,154.75 180 top
R108  0  [R0603@1]  55.39,149.69 180 top
R109  100K  [R0805]  48.23,112.53 180 top
R110  100K  [R0805]  26.13,37.86 0 top
R111  100K  [R0805]  22.07,37.86 0 top
R112  100K  [R0805]  18,37.86 0 top
R113  100K  [R0805]  27.66,56.91 0 top
R114  100K  [R0805]  23.34,56.91 0 top
R115  100K  [R0805]  19.02,56.91 0 top
R116  100K  [R0805]  28.42,68.85 0 top
R117  100K  [R0805]  24.35,68.85 0 top
R118  100K  [R0805]  19.78,68.85 0 top
R119  270  [R0805]  25.62,43.19 180 top
R120  240k  [R0805]  18.51,51.07 0 top
R121  270  [R0805]  27.66,59.96 180 top
R122  240k  [R0805]  34.26,68.08 0 top
R123  270  [R0805]  27.91,71.39 180 top
R124  240k  [R0805]  30.7,74.69 90 top
R126  100K  [R0805]  16.48,90.69 90 top
RF1  [TFM-110-02-SM-D-A-K]  106.29,155.11 180 top
RF1_FIFO  [JP2Q]  133.32,145.81 0 top
RF1_GPIO  [JP2Q]  117.7,130.8 0 top
RF2  [TFM-110-02-SM-D-A-K]  75.81,155.11 180 top
RF2_FIFO  [JP2Q]  63.75,126.5 0 top
RF2_GPIO  [JP2Q]  5.3,138.11 0 top
RF3  [TFM-110-02-SM-D-A-K]  45.03,155.11 180 top
RF4  [TFM-110-02-SM-D-A-K]  14.55,155.11 180 top
RS-232  [F09VP]  131.29,71.39 270 top
S1  [PBTH]  124.61,137.96 0 top
S2  [PBTH]  124.61,117.26 0 top
S3  [PBTH]  39.09,76.47 0 top
S4  [PBTH]  58.14,129.81 180 top
SL1  [02P]  123.16,102.12 180 top
SL2  [02P]  120.37,117.87 270 top
SW2_JMP  [JP1]  129.26,106.69 0 top
TP4  TST_PNT  [TST_PNT]  115.54,157.01 0 top
TP8  TST_PNT  [TST_PNT]  117.32,155.74 0 top
TP10  TST_PNT  [TST_PNT]  115.51,159.55 0 top
TP13  TST_PNT  [TST_PNT]  116.78,158.28 0 top
TP20  TST_PNT  [TST_PNT]  104.77,145.07 0 top
TP21  TST_PNT  [TST_PNT]  101.57,147.59 0 top
TP22  TST_PNT  [TST_PNT]  43.45,146.06 0 top
TP23  TST_PNT  [TST_PNT]  40.61,148.35 0 top
TP24  TST_PNT  [TST_PNT]  50.52,156.98 0 top
TP25  TST_PNT  [TST_PNT]  52.8,155.71 0 top
TP26  TST_PNT  [TST_PNT]  50.57,159.55 0 top
TP27  TST_PNT  [TST_PNT]  53.06,158.31 0 top
TVS1  SMAJ5.0CA  [DO214AC]  83.21,25.71 180 top
TVS2  SMAJ5.0CA  [DO214AC]  98.95,25.87 180 top
TVS3  SMAJ5.0CA  [DO214AC]  113.43,26.12 180 top
TVS4  SMAJ5.0CA  [DO214AC]  128.32,26.48 180 top
U3  PS8802  [SO08]  117.32,74.69 90 top
U4  PS8802  [SO08]  117.32,66.81 90 top
U$1  PLC_SMB25  [PLC_SMB25]  8.35,47 180 top
U$2  PLC_SMB25  [PLC_SMB25]  8.35,60.21 180 top
U$3  PLC_SMB25  [PLC_SMB25]  8.35,72.4 180 top
U$4  AC_DC_12V  [AC_DC_12V]  17.24,80.78 90 bottom
U$5  PTH08080  [PTH08080]  20.8,133.87 0 bottom
U$6  WATT_PULSE  [WATT_PULSE]  17.24,113.04 0 top
U$7  PTH08080  [PTH08080]  41.37,126.25 0 top
U$8  741T45  [DBV_R-PDSO-G6]  37.05,135.14 90 top
U$9  741T45  [DBV_R-PDSO-G6]  43.91,136.16 90 top
U$10  74132  [74132]  12.16,97.55 270 top
U$14  [CONN34]  56.1,104.66 0 top
WMBUS_UART0  [JP2Q]  124.43,147.08 0 top
WMBUS_UART1  [JP2Q]  128.75,129.55 0 top
X1  FFKV2  [FFKV2]  43.24,9.13 0 top
X2  FFKV2  [FFKV2]  57.12,9.16 0 top
X3  FFKV2  [FFKV2]  72.11,9.17 0 top
X4  FFKV2  [FFKV2]  85.97,9.21 0 top
X5  FFKV2  [FFKV2]  99.24,9.19 0 top
X6  FFKV2  [FFKV2]  112.4,9.19 0 top
X7  FFKV2  [FFKV2]  125.67,9.21 0 top
XT1  XT1  [CM200T]  74.42,84.52 0 top
XT2  XT2  [X905]  59.18,66.43 90 top
Z1  [2,54/0,8]  35.02,50.3 0 top
Z2  [2,54/0,8]  41.63,55.38 0 top
Z3  [2,54/0,8]  41.4,81.45 0 top
ZXING  [2,54/0,8]  20.5,95.28 0 top

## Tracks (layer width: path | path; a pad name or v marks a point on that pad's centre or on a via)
A0CLK  (via drill 0.5)
  Top 0.254: v69.24,87.59 68.8,86.88 68.8,77.99 70.33,76.47 70.63,76.47 71.3,75.8 MSP430F47187.75 | R82.2 32.91,158.84 v32.74,159.02
  Bottom 0.254: v69.24,87.59 69.26,87.59 69.54,87.87 69.54,102.1 72.11,104.91 72.11,163.08 69.06,164.6 38.32,164.6 v32.74,159.02
A0CS  (via drill 0.5)
  Top 0.254: MSP430F47187.51 84.24,75.4 v84.81,75.96 | v31.21,156.98 31.47,156.98 31.57,157.09 R81.2
  Bottom 0.254: 84.81,76.21 v84.81,75.96 82.01,78.75 82.01,82.05 80.74,83.32 80.74,87.64 79.46,88.94 79.46,93.8 80.74,95.12 80.74,109.99 78.96,111.77 | 78.96,111.77 | 78.96,111.77 78.92,111.77 78.92,113.51 80.74,115.33 80.74,124.47 86.08,129.81 86.08,147.33 83.28,150.13 83.28,162.83 82.01,164.1 72.11,164.1 72.08,164.07 72.08,164.05 69.57,165.62 36.8,165.62 31.21,160.03 v31.21,156.98 | 78.96,111.77
A0RXD
  Bottom 0.254: EZRF_EN.4 129.23,159.5 131.03,161.3 131.03,162.32 131.04,162.32 EZRF.6
A0SIMO  (via drill 0.5)
  Top 0.254: MSP430F47187.79 68.35,72.1 67.79,72.66 67.79,99.33 70.58,102.12 70.61,102.12 70.61,114.85 v72.99,117.11 | R83.2 30.55,160.64 29.18,159.27 v28.93,159.27 28.93,151.14 35.53,144.54 63.22,144.54 v65.5,142.25 66.01,142.76 v73.38,142.76
  Top 0.406: EZRF_EN.1 126.72,154.95 127.99,156.22 v132.81,156.22
  Bottom 0.254: EZRF_EN.1 122.65,154.95 121.38,156.22 121.38,165.62 118.84,168.16 36.8,168.16 28.93,160.29 v28.93,159.27 | v72.99,117.11 72.99,142.35 v73.38,142.76 | v65.5,142.25 65.5,135.9 2.4RF_UART.4 64.23,135.39
  Bottom 0.406: EZRF_EN.1 126.72,154.95 125.7,153.94 WMBUS_UART0.4 | J1.2 138.4,106.69 139.67,107.96 139.67,154.7 138.15,156.22 v132.81,156.22
A0SOMI  (via drill 0.5)
  Top 0.254: MSP430F47187.78 68.61,72.6 68.3,72.91 68.3,99.07 71.09,101.87 71.09,113.04 v75.15,117.11 | R84.2 30.55,162.42 27.91,159.78 v26.64,159.78 | v75.66,135.9 67.28,135.9 66.26,136.92 63.72,136.92 62.45,135.65 | 62.45,135.65 2.4RF_UART.2 | 62.45,135.65 62.45,137.17 59.66,139.97 v36.29,139.97
  Bottom 0.254: EZRF_EN.3 129.23,154.98 127.99,156.22 122.91,156.22 122.14,156.98 122.14,166.13 119.1,169.18 34.77,169.18 26.64,161.05 v26.64,159.78 26.64,155.46 36.29,145.81 v36.29,139.97 | v75.15,117.11 75.15,135.39 v75.66,135.9
  Bottom 0.406: WMBUS_UART0.2 123.16,148.09 124.18,147.08 128.49,147.08 129.26,147.84 129.26,154.7 129.23,154.72 EZRF_EN.3 136.62,154.95 137.89,153.68 J2.2
A0TXD
  Bottom 0.254: EZRF_EN.2 126.69,159.55 124.68,161.56 124.68,162.06 124.69,162.07 EZRF.1
A1RXD  (via drill 0.5)
  Top 0.254: v76.47,67.34 76.42,67.4 75.31,66.31 74.39,66.31 71.1,69.6 MSP430F47187.84 69.4,69.6 69.39,69.58 69.36,69.61 67.81,69.61 67.25,70.17 67.25,99.56 70.07,102.37 70.07,115.58 66.77,118.88 PLC_UART.3 64.99,119.14
  Top 0.406: JP12.3 109.7,77.23 v112.49,80.02 | v126.72,112.03 126.72,124.73 v125.45,126.25
  Bottom 0.254: v76.47,67.34 78.71,65.29 85.57,65.29 87.57,63.28 102.61,63.28 103.86,64.53 103.86,74.94 JP12.3
  Bottom 0.406: v112.49,80.02 112.49,83.07 121.13,91.71 121.13,93.74 126.72,99.33 v126.72,112.03 | WMBUS_UART1.2 127.22,130.82 125.45,128.79 v125.45,126.25
A1TXD  (via drill 0.5)
  Top 0.254: 70.86,69.1 MSP430F47187.85 70.84,69.1 74.14,65.8 76.68,65.8 76.65,65.82 v76.65,65.87 | v55.34,72.4 55.09,72.4 54.58,72.91 54.58,74.94 55.09,75.45 57.45,75.45 63.22,80.89 63.22,83.32 v62.71,83.58 | v61.95,87.64 61.95,98.31 63.22,99.58 63.22,106.18 v61.18,108.22 | v61.69,112.28 61.69,114.06 v62.45,115.23
  Top 0.406: WMBUS_UART1.4 132.05,130.82 132.81,130.06 132.81,92.21 136.37,88.66 136.37,54.62 134.59,52.34 119.35,52.34 116.3,55.38 107.41,55.38 103.86,58.69 v103.86,60.72
  Bottom 0.254: v55.34,72.4 56.1,71.64 56.1,63.51 57.88,61.73 62.2,61.73 66.77,66.31 76.42,66.31 76.68,66.05 76.65,66.03 v76.65,65.87 76.65,65.82 77.74,64.73 85.36,64.73 85.57,64.53 85.58,64.55 87.37,62.62 101.95,62.62 v103.86,60.72 | v62.71,83.58 62.71,86.88 v61.95,87.64 | v61.18,108.22 61.18,109.23 60.93,109.49 60.93,111.52 v61.69,112.28 | v62.45,115.23 PLC_UART.1 | 104.36,62.75 104.24,62.62
  Bottom 0.406: v103.86,60.72 103.86,62.24 104.36,62.75 JP13.3
AGND  (via drill 0.5, 0.6, 0.7)
  Top 0.254: 77.8,49.01 77.83,48.97 C5.1 | MSP430F47187.18 79.8,60.13 79.8,61.02 79.6,61.23 74.65,61.23 74.3,60.88 MSP430F47187.7 74.3,60.81 v73.88,61.23
  Top 0.406: C14.2 37.31,48.76 v36.88,48.32 | C19.2 55.49,45.58 v56.36,44.72 | C17.2 52.32,52.62 v51.79,52.08 | C34.2 69.26,41.21 v69.82,40.65 | C33.2 65.88,48.65 v65.25,48.02 | C5.1 76.4,49.26 v76.17,49.03 | C16.2 39.24,41.11 v40.03,40.12 | C3.- 71.8,54.82 v72.11,55.13
  Top 0.61: 84.58,29.58 D2.A | 84.58,29.58 D4.A | 84.58,29.58 84.81,29.81 84.81,28.97 v83.54,27.7 | D6.A 99.46,29.37 D8.A 100.42,29.35 v101.32,28.46 | D18.A 114.98,29.37 D20.A 111.53,28.41 v112.24,27.95 | C20.2 89.59,37.39 89.63,37.35 89.67,37.39 C25.2 92.65,40.93 v92.43,41.16 | 107.74,37.02 107.92,36.84 107.92,38.11 v107.21,38.49 | 107.74,37.02 C37.2 | C23.2 107.7,37.06 107.74,37.02 | 122.59,37.03 C39.2 | C36.2 122.59,37.03 | 122.59,37.03 122.65,37.1 | D24.A 129.48,29.5 129.51,29.48 129.56,29.53 D22.A 129.51,29.6 129.51,28.97 v128.49,27.95 | C38.2 133.73,39.53 v134.08,39.89 | 122.59,37.03 122.59,37.16 v121.1,38.37 | C1.1 81.58,48.09 v81.25,47.76 | C22.2 76.5,38.8 v75.66,39.64
  pour GND: 140.18,1.28 140.43,45.48 132.3,52.08 84.81,52.08 80.23,56.65 80.23,61.73 79.98,61.99 40.86,61.99 31.72,71.13 22.83,71.13 1.24,49.03 0.99,0.77
AVCC  (via drill 0.7, 0.9)
  Top 0.254: 79.5,49.16 79.53,49.12 C5.2 | C3.+ 74.6,53.4 74.65,53.35 74.8,53.5 MSP430F47187.8
  Top 0.406: C5.2 79.47,49.21 79.52,49.16 79.52,48.07 78.4,46.95 R7.2
  Top 0.61: D7.C 99.39,38.01 D5.C 99.44,38.09 100.27,38.09 v101.06,38.87 | D19.C 115.08,38.04 D17.C 115.29,38.19 115.29,39.38 v115.84,39.76 | v130.83,39.76 129.76,39.64 129.61,39.48 129.61,38.21 D21.C 129.81,38.16 126.66,38.16 126.46,38.37 126.41,38.32 D23.C | D1.C 84.58,38.14 84.5,38.06 D3.C | C3.+ 76.35,53.43 79.47,50.3 79.47,49.29 79.5,49.26 C5.2
  Top 0.813: D1.C 84.6,38.16 v86.08,39.64 | C5.2 79.53,45.54 v79.47,43.95
  VCC 0.813: v130.83,39.76 v115.84,39.76 101.7,39.76 101.06,39.13 v101.06,38.87 90.39,38.87 88.36,36.84 86.33,36.84 86.33,39.38 v86.08,39.64 86.08,42.68 83.54,43.95 v79.47,43.95
B0CLK  (via drill 0.5)
  Top 0.254: MSP430F47187.72 72.8,76.79 71.6,77.99 71.09,77.99 70.33,78.75 70.33,81.29 70.61,81.57 v70.68,81.57 | v84.04,138.44 v93.44,138.44 | R71.2 94.25,159.07 v94.2,159.02
  Bottom 0.254: v70.68,81.57 70.68,81.7 70.33,82.05 70.33,84.34 71.09,85.1 71.09,86.63 71.6,87.13 71.6,102.63 76.93,108.22 76.93,114.57 78.71,116.34 78.71,137.43 79.73,138.44 v84.04,138.44 | v93.44,138.44 93.44,158.25 v94.2,159.02
B0CS  (via drill 0.5)
  Top 0.254: MSP430F47187.52 82.8,74.41 83.03,74.18 85.06,74.18 v85.82,74.94 | R70.2 98.05,157.28 98.01,157.24 v95.98,157.24
  Bottom 0.254: v85.82,74.94 85.82,68.34 85.87,68.34 88.77,65.44 96.35,65.44 96.36,65.46 96.38,65.44 100.66,65.44 101.32,66.1 101.32,83.83 103.89,86.41 108.87,86.41 109.16,86.7 109.16,86.73 112.49,90.06 112.49,101.36 110.97,102.88 110.97,125.23 99.79,136.41 99.79,156.73 99.28,157.24 v95.98,157.24
B0SIMO  (via drill 0.5)
  Top 0.254: MSP430F47187.74 71.8,76.27 71.09,76.97 70.58,76.97 69.31,78.24 69.31,86.37 v70.71,87.77 | v81.5,161.81 96.49,161.81 97.51,160.79 98.01,160.79 98.04,160.82 R72.2
  Bottom 0.254: v70.71,87.77 70.71,102.5 76.42,108.47 76.42,114.82 76.68,115.07 77.19,115.58 77.19,160.29 78.71,161.81 v81.5,161.81
B0SOMI  (via drill 0.5)
  Top 0.254: MSP430F47187.73 72.3,76.53 71.34,77.48 70.84,77.48 69.82,78.5 69.82,85.61 v70.15,85.94 | R73.2 79.9,162.65 78.46,164.1 71.85,164.1 69.82,162.06 v69.82,161.56
  Bottom 0.254: v70.15,85.94 70.15,86.04 70.07,86.12 69.06,86.12 68.12,87.06 68.12,87.69 69.06,88.66 69.06,102.37 71.6,105.17 71.6,158.76 69.82,160.54 v69.82,161.56
B1CLK  (via drill 0.5)
  Top 0.254: 76.4,70.4 76.42,70.37 | v76.37,70.4 76.4,70.4 | MSP430F47187.80 75.2,71.6 76.4,70.4 | v61.59,80.53 61.59,80.67 58.65,83.61 58.65,87.39 58.14,87.9 v44.42,87.9
  Top 0.406: U$14.25 50.69,109.92 v49.5,108.72 | v43.4,105.68 43.4,90.94 v44.42,89.93
  Bottom 0.254: v61.59,80.53 61.79,80.3 61.79,71.03 62.45,70.37 76.42,70.37 76.4,70.4 v76.37,70.4 | v44.42,87.9 v44.42,89.93
  Bottom 0.406: 49.75,108.72 v49.5,108.72 46.45,108.72 v43.4,105.68
B1CS  (via drill 0.5)
  Top 0.254: v72.61,61.99 71.34,61.99 67.03,57.67 54.58,57.67 46.2,66.05 46.2,84.85 48.23,86.88 v54.07,86.88 | MSP430F47187.53 82.3,75.25 82.29,75.25 82.32,75.22 82.32,74.38 80.52,72.58 80.52,72.59 | v80.87,69.08 80.87,69.23 80.49,69.61 80.48,72.59 80.52,72.59 | v81.25,67.37 81.25,63.51 83.66,61.36 v84.68,60.31 | 80.52,72.59 80.55,72.59 82.3,74.35
  Top 0.406: U$14.26 57.71,109.92 57.63,109.99 v61.77,110.02
  Bottom 0.254: v80.87,69.08 80.87,67.7 v81.25,67.37 | v72.61,61.99 72.74,62.12 77.31,62.12 79.73,60.21 84.55,60.21 84.65,60.31 v84.68,60.31 | v61.77,110.02 64.49,109.99 66.01,108.47 66.01,90.18 64.74,88.91 56.1,88.91 v54.07,86.88
B1SIMO  (via drill 0.5)
  Top 0.254: MSP430F47187.82 73.4,70.6 v74.8,69 | v58.14,70.62 55.34,70.62 v55.09,70.88
  Top 0.406: U$14.27 50.18,111.19 44.93,105.93 44.93,91.2 v46.2,89.93
  Bottom 0.254: v58.14,70.62 58.64,71.13 60.17,71.13 61.95,69.35 74.65,69.35 v74.8,69 | v55.09,70.88 54.07,72.15 54.07,81.55 46.2,89.42 v46.2,89.93
B1SOMI  (via drill 0.5)
  Top 0.254: v60.93,77.48 62.2,77.48 63.72,79.26 63.72,107.71 62.71,108.72 62.71,110.76 | MSP430F47187.81 74.43,71.1 v76.27,69.14
  Top 0.406: U$14.28\ 62.28,111.19 62.71,110.76
  Bottom 0.254: v76.27,69.14 76.21,69.14 76.17,69.1 75.41,69.86 62.2,69.86 61.18,70.88 61.18,76.97 60.93,77.23 v60.93,77.48
CCA_A  (via drill 0.5)
  Top 0.254: MSP430F47187.45 87.31,71.1 89.89,73.67 89.89,80.28 87.6,82.56 84.81,82.56 82.52,84.85 v82.54,84.85 | R68.2 91.28,153.81 88.11,150.63 v88.11,149.87
  Bottom 0.254: v88.11,149.87 LED_EN.1 84.3,116.34 84.3,112.53 81.99,110.25 81.99,89.66 82.54,89.14 v82.54,84.85
CCA_B  (via drill 0.5)
  Top 0.254: MSP430F47187.44 87.57,70.6 90.39,73.42 90.42,79.9 90.42,81.01 v88.89,82.49 | R79.2 34.92,153.33 v34.77,153.17 | v55.6,137.93 55.85,137.93 60.17,133.62 60.17,124.47 60.93,123.71 65.76,123.71 67.28,122.19 83.79,122.19 88.11,117.87 LED_EN.3
  Bottom 0.254: v88.89,82.49 88.89,85.64 91.92,88.66 91.92,92.47 86.6,97.79 86.6,116.11 LED_EN.3 | v55.6,137.93 55.6,146.32 48.74,153.17 v34.77,153.17 34.51,153.17
COM0  (via drill 0.5)
  Top 0.254: MSP430F47187.56 80.8,76.78 v83.18,79.08 | v83.54,94.25 83.54,96.02 LCD1.P$18
  Bottom 0.254: v83.54,94.25 84.07,93.69 84.07,89.93 83.54,89.42 83.54,79.44 v83.18,79.08 83.15,79.06
COM1  (via drill 0.5)
  Top 0.254: MSP430F47187.57 80.32,77.11 82.49,79.95 83.87,79.95 v84.4,79.51 | v85.31,94.25 85.31,95.26 LCD1.P$17
  Bottom 0.254: v84.4,79.51 84.58,79.79 84.58,80.56 84.53,93.54 84.53,93.71 85.06,94.25 v85.31,94.25
COM2  (via drill 0.5)
  Top 0.254: MSP430F47187.58 79.8,77.4 82.29,80.45 84.75,80.45 v85.57,79.77 | v86.84,95.52 87.09,95.52 104.87,113.3 LCD1.P$16
  Bottom 0.254: v85.57,79.77 85.57,85.86 86.84,87.13 v86.84,95.52
COM3  (via drill 0.5)
  Top 0.254: MSP430F47187.59 79.3,77.77 82.06,80.91 86.02,80.91 v86.84,80.53 | v88.11,95.01 90.14,95.01 LCD1.P$15
  Bottom 0.254: v86.84,80.53 86.84,85.1 89.38,87.64 89.38,93.74 v88.11,95.01
DGND  (via drill 0.5, 0.6, 0.7, 0.8)
  Top 0.254: 62.94,64.1 MSP430F47187.95 | JP5.2 122.91,88.4 | XT2.2 59.18,66.33 59.15,66.31 60.97,68.12 C12.1 | C11.- 87.98,73.54 v87.35,73.16 | C13.1 57.46,79.26 | 57.46,79.26 57.46,79.35 | C10.1 61.91,64.31 v61.44,64.78 | v79.14,70.17 79.14,70.19 78.8,70.54 MSP430F47187.60 | XT1.P3 74.42,85.59 74.39,85.61 74.39,86.88 | C9.1 80.63,84.53 79.95,85.2 79.01,85.2 78.99,85.23 C8.- 76.96,85.21 76.88,85.13 C6.2 | 57.46,79.26 57.37,79.26 57.45,79.34 | R2.1 101.72,120.01 101.82,119.9 101.78,119.85 R3.1 | MSP430F47187.67 75.3,74.54 v76.42,73.42 | v22.58,150.38 22.07,150.89 C44.- 21.94,152.28 21.81,152.41 21.98,152.58 C45.1 | RF4.2 11.17,149.39 v10.64,148.86 | RF3.1 48.2,149.39 v48.99,148.6 | RF3.19 48.2,160.82 v50.01,162.57 | v85.57,150.89 86.33,151.65 C43.1 86.33,152.67 83.79,152.67 83.13,152 C42.- | RF1.19 109.47,160.82 v110.21,161.56 | RF1.1 109.47,149.39 v109.95,149.62 | 101.82,120.15 101.66,120.32 R1.1 102.84,121.93 v103.09,122.19 | RF2.2 74.29,147.74 v73.88,147.33 | R40.1 67.45,150.72 67.53,150.63 67.45,150.55 R10.1 67.45,153.34 v67.79,153.68 | U$10.P$7 11.51,93.09 v11.28,92.52 | R49.1 11.15,100.85 v10.89,100.6 | R38.1 29.18,101.1 v29.69,101.61
  Top 0.406: 62.94,64.1 62.99,64.15 C10.1 | 62.94,64.1 | C2.- 61.69,72.15 61.86,72.31 C4.1 | R2.1 101.82,120.15 | C13.1 57.46,77.57 56.61,76.72 52.29,76.72 JTAG.9 52.04,77.74 v53.06,78.75 | 58.14,66.31 59.15,66.31 | Q3.E 112.43,69.3 v113,70.22 | U$14.5 57.3,97.22 57.37,97.29 57.45,97.22 U$14.6 59.23,97.22 v59.91,96.53 | v32.23,134.63 32.74,135.14 U$8.5 U$8.2 | U$9.2 46.71,136.16 v47.21,135.65 | U3.5 113.38,76.59 113,76.97 113,77.48 v113.25,77.74 | 741G157_1.2 7.84,86.78 7.53,86.46 4.12,86.46 | R48.2 4.03,86.37 4.12,86.46 | 4.12,86.46 4.12,87.99 v4.54,88.4 | R39.1 36.04,52.34 35.62,52.76 R32.1 v37.05,54.11 | R42.1 25.12,80.78 v24.34,81.42 | 741G57.2 v22.32,79.77 | C57.1 13.94,80.78 v13.43,81.04 | R46.1 3.53,111.01 v3.78,111.26
  Top 0.61: DGND.4 DGND.3 DGND.2 DGND.1 | C7.1 72.07,86.33 72.61,86.88 74.39,86.88 | C6.2 76.88,86.42 76.42,86.88 74.39,86.88 | 74.39,86.88 v74.39,90.44 | 57.45,79.34 58.82,79.34 v59.15,79.01 | v58.14,72.15 C2.- | R9.2 40.86,126 40.84,125.97 35.05,125.97 | 21.58,133.59 21.56,133.62 R8.2 21.65,133.78 | U$7.2 35.05,125.97 | 35.05,125.97 35.02,126 | 21.65,133.78 21.56,133.87 | U$5.2 21.84,133.59 21.65,133.78
  Bottom 0.61: v37.05,54.11 35.28,55.89 35.28,69.1 39.09,72.91 S3.1 | S3.1
  pour GND: 140.43,47.51 140.18,169.18 0.73,169.94 0.73,52.59 0.99,52.34 2.51,52.34 22.07,71.89 32.23,71.89 41.12,63 79.98,63 81,61.99 81,56.91 85.06,52.84 132.56,52.84 140.43,46.49
DVCC  (via drill 0.5, 0.7)
  Top 0.254: 124.34,123.04 124.43,122.95 | R6.2 124.34,123.04 | 124.34,123.04 124.23,123.15 | R11.1 57.46,82.14 v58.14,82.82 | RF4.9 21.84,154.47 21.94,154.57 | 21.94,154.57 22.07,154.7 C44.+ 20.67,155.08 v20.54,155.21 | C45.2 25.88,154.19 25.62,154.44 22.07,154.44 21.94,154.57 | C43.2 86.14,154.25 86.08,154.19 83.54,154.19 83.03,154.7 C42.+ 82.88,154.8 82.54,154.47 RF2.9 79.5,154.47 v80.23,155.21 | R109.2 47.38,111.68 v46.45,110.76 | v6.73,92.95 6.85,92.95 7.85,91.95 741G157_1.5
  Top 0.406: R6.2 124.18,122.95 124.23,123 | U$14.8 59.74,98.48 v60.42,97.8 | v46.71,134.38 45.88,135.21 U$9.1 44.99,135.21 44.93,135.14 44.42,135.14 43.4,136.16 U$9.5 41.63,136.16 41.37,135.9 41.37,135.14 40.42,134.19 U$8.1 | R41.2 79.98,150.38 v80.23,150.13 | IS02.4 v37.31,56.65 | v34.01,77.74 33.13,78.61 ISO3.4 33.07,80.71 32.99,80.78 | v21.56,82.05 21.07,81.57 741G57.3 20.99,80.72 20.8,80.53 20.04,80.53 19.28,79.77 741G57.5 18.26,79.77 17.75,79.77 17.24,80.28 C57.2 | 18.71,97.09 18.77,97.04 | 18.71,97.09 v18.71,97.12 | U$10.P$14 18.26,97.55 18.71,97.09
  Top 0.61: DVCC.4 DVCC.3 DVCC.2 DVCC.1 | 124.18,122.95 v124.18,124.98 | R5.2 124.23,131.13 v124.18,131.08 | ISO1.4 30.88,53.28 v29.69,52.08
  Top 0.813: J5.1 39.34,60.97 38.07,62.24 38.07,67.07 38.83,67.83 PWR_JMP.2
  VCC 0.61: J5.1 37.31,58.69 v37.31,56.65 36.04,55.38 v29.69,52.08
  pour VCC: 0.83,169.96 0.83,52.41 1.09,52.16 2.59,52.16 22.07,71.64 32.48,71.64 41.32,62.45 58.52,62.42 58.39,93.99 91.16,93.99 91.23,62.04 81,61.99 81,56.91 85.06,52.84 132.56,52.84 139.16,46.24 139.16,169.84 139.14,169.86 0.99,169.86 0.86,169.99
EXT
  Bottom 0.61: PWR_JMP.3 48.48,70.37 JTAG.4
FA  (via drill 0.5)
  Top 0.254: U$10.P$1 12.92,97.55 v13.44,97.12 | 12.67,91.48 12.67,91.45 | v13.43,95.26 13.43,93.23 15.21,91.45 15.21,91.48
  Top 0.406: R126.2 16.48,91.45 16.45,91.48 15.21,91.48 12.67,91.48 741G157_1.4
  Bottom 0.254: v13.43,95.26 v13.44,97.12
FB  (via drill 0.5)
  Top 0.254: 741G157_1.1 6.89,89.74 7.34,90.18 8.39,90.18 8.78,89.79 8.78,88.99 8.86,88.91 8.84,88.89 741G157_1.3 8.79,88.98 8.61,89.17 | U$10.P$4 8.18,95.6 8.1,95.52
  Top 0.406: U$14.13 52.47,102.3 v51.28,101.1 | v42.13,102.12 38.07,102.12 v36.8,100.34 | 26.39,100.85 26.55,101.02 R38.2 R36.2 26.13,101.1 26.39,100.85 | 26.39,100.85 26.55,100.69 26.55,100.22 25.66,99.33 v25.62,99.33 26.39,100.09 26.39,100.85 | v10.01,99.56 9.11,99.58 8.1,98.56 8.1,95.52 8.1,94.5 v9.11,93.48 | 8.61,89.17 8.61,88.4 v9.62,87.39
  Bottom 0.406: v51.28,101.1 50.52,101.1 50.01,100.6 43.66,100.6 v42.13,102.12 | v36.8,100.34 26.64,100.34 v25.62,99.33 10.26,99.31 v10.01,99.56 | v9.11,93.48 9.11,87.9 v9.62,87.39
FC  (via drill 0.5)
  Top 0.254: U$14.14 59.99,102.3 v60.17,102.12 | v38.58,88.15 31.97,88.15 v31.47,88.66 | 13.99,102.63 14.28,102.33 14.28,100.94 14.19,100.85 R49.2 | 13.99,102.63 3.27,102.63 2.26,101.61 2.26,92.72 3.53,91.45 6.83,91.45 6.86,91.48 741G157_1.6 | 14.22,93.77 14.19,93.74 | v14.32,93.77 14.22,93.77 | U$10.P$9 14.75,94.3 14.22,93.77 | 17.5,100.6 17.5,102.37 v17.2,102.9 | 13.99,102.63 13.99,102.93 v14.45,103.39
  Top 0.406: 17.75,100.85 R37.2 17.66,100.76 17.5,100.6 | 14.7,100.6 14.45,100.85 R49.2 14.28,99.16 14.19,99.07 10.89,99.07 v9.88,98.06 | 741G157_1.6 6.89,91.52
  Bottom 0.254: 59.91,102.37 v60.17,102.12 | v31.47,88.66 30.45,88.66 29.94,89.17 | v14.32,93.77 14.32,97.47 14.96,98.06 | v17.2,102.9 15.28,102.9 v14.45,103.39
  Bottom 0.406: 29.94,89.17 29.94,96.28 28.16,98.06 14.96,98.06 v9.88,98.06 | 59.91,102.37 59.41,102.37 50.01,91.96 39.59,91.96 38.58,90.94 v38.58,88.15
FET
  Bottom 0.61: PWR_JMP.1 46.45,65.29 JTAG.2
FIFO
  Top 0.254: 104.85,145.07 104.87,145.05 | TP20.TP 104.85,145.07 | RF1.2 104.77,145.15 104.85,145.07
FIFO1
  Top 0.254: TP22.TP 43.66,146.06 43.51,146.21 RF3.2
FIFO_A  (via drill 0.5)
  Top 0.254: R66.2 98.19,150.3 98.27,150.38 98.27,148.6 104.11,143.01 117.57,143.01 | R30.1 117.83,152.92 119.6,151.14 119.6,145.05 117.57,143.01 | 117.57,143.01 125.19,143.01 129.26,147.08 RF1_FIFO.2
  Top 0.406: WMBUS_UART1.3 128.75,129.55 128.75,133.36 132.81,137.43 132.81,138.7 v134.59,140.47
  Bottom 0.406: WMBUS_UART0.3 130.78,145.81 RF1_FIFO.2 132.3,147.08 133.32,146.06 133.32,141.49 134.34,140.47 v134.59,140.47
FIFO_B  (via drill 0.5)
  Top 0.254: RF2_FIFO.2 62.48,130.34 2.4RF_UART.3 | 35.33,148.15 35.28,148.09 | v35.35,148.15 35.33,148.15 | R77.2 36.18,149 35.33,148.15 | 57.88,152.67 v57.88,152.46 | R106.1 57.37,153.17 57.88,152.67 | v59.66,156.98 59.66,154.44 57.88,152.67
  Bottom 0.254: v59.66,156.98 59.66,159.52 55.34,163.84 39.59,163.84 32.99,157.24 32.99,150.13 v35.35,148.15 | 2.4RF_UART.3 64.74,132.85 63.72,133.87 63.72,146.32 v57.88,152.46
FIFOP
  Top 0.254: RF1.4 103.63,150.66 101.57,148.6 TP21.TP
FIFOP1
  Top 0.254: RF3.4 41.9,150.66 40.61,149.36 TP23.TP 40.61,148.09
FIFOP_A  (via drill 0.5)
  Top 0.254: R67.2 98.05,152.12 98.01,152.16 97.25,152.16 96.49,151.4 96.49,147.84 102.84,141.74 125.45,141.74 129.51,145.81 130.53,145.81 133.32,145.81 RF1_FIFO.4 | RF1_FIFO.4 134.59,147.33 | R60.1 123.39,154.72 129,149.11 132.56,149.11 RF1_FIFO.4 | RF1_FIFO.4 134.34,147.08
  Top 0.406: 130.53,145.81 130.53,145.55 129.51,144.54 v129.51,143.52
  Bottom 0.406: WMBUS_UART0.1 123.16,144.28 123.92,143.52 v129.51,143.52 131.03,142 131.03,136.16 128.75,133.87 128.75,129.3 127.73,128.28 WMBUS_UART1.1
FIFOP_B  (via drill 0.5)
  Top 0.254: R78.2 35.35,151.47 v34.77,150.89 | R107.1 56.22,155.57 v56.61,155.97
  Bottom 0.254: 62.71,132.85 2.4RF_UART.1 | RF2_FIFO.4 65.02,130.54 62.71,132.85 | 62.71,132.85 59.15,132.85 57.37,134.63 | 57.37,134.63 56.87,135.14 | 57.37,134.63 54.33,137.68 54.33,146.32 49.75,150.89 v34.77,150.89 33.5,152.16 33.5,155.71 39.34,161.05 54.58,161.05 56.61,159.52 v56.61,155.97
I1+  (via drill 0.6)
  Top 0.254: v82.27,46.75 84.55,46.75 85.14,47.33 85.14,50.23 84.3,51.07 80.49,51.07 75.8,55.76 MSP430F47187.10
  Top 0.61: 89.59,35.69 89.61,35.7 | 89.59,35.69 C20.1 88.75,35.69 88.11,36.33 88.11,38.62 v89.12,39.64 | R26.2 89.56,35.65 89.59,35.69 | C21.1 81.34,44.4 81.38,44.44 81.35,44.46 | 81.35,44.51 81.34,44.5 C21.1 | v82.27,46.75 82.27,46.39 81.35,45.48 81.35,44.56 81.25,44.46 81.34,44.37 C21.1
  Bottom 0.61: v89.12,39.64 89.12,41.41 83.79,46.75 v82.27,46.75
I1-
  Top 0.254: 83.03,44.39 85.06,44.39 85.82,45.15 85.82,50.56 84.81,51.57 80.74,51.57 76.3,56.02 MSP430F47187.11
  Top 0.61: R28.2 76.55,35.98 76.45,36.08 76.5,36.13 C22.1 77.45,36.25 77.9,36.69 77.9,39.99 80.69,42.79 82.93,42.79 83.05,42.91 83.05,44.28 83,44.34 83.03,44.36 C21.2 | C21.2 83,44.36 82.93,44.28 | C21.2 83.04,44.37 83.03,44.39 83,44.41
I2+  (via drill 0.6)
  Top 0.254: MSP430F47187.12 76.8,56.28 81,52.08 93.7,52.08 94.2,51.57
  Top 0.406: 94.67,44.5 94.67,51.1 94.2,51.57
  Top 0.61: 105.05,32.85 104.91,32.99 R29.2 104.71,32.99 104.74,33.03 C23.1 103.94,35.36 103.25,35.8 103.25,42.02 v102.86,42.41 | C24.1 94.79,44.31 94.76,44.28 | 94.64,44.36 C24.1 | 94.66,44.51 94.67,44.5 C24.1 | v93.7,42.68 93.7,43.95 93.95,44.21 94.71,44.21 94.67,44.25 C24.1
  Bottom 0.61: 93.95,42.68 v93.7,42.68 93.7,42.94 94.71,43.95 101.57,43.95 102.86,42.66 v102.86,42.41
I2-
  Top 0.254: MSP430F47187.13 77.3,56.54 81.25,52.59 95.22,52.59 96.24,51.57
  Top 0.406: C24.2 96.37,51.44 96.24,51.57
  Top 0.61: 92.45,35.7 92.46,35.69 C25.1 92.87,35.69 92.88,35.67 93.67,35.67 93.95,35.95 93.95,41.59 96.39,42.76 96.39,44.18 96.34,44.23 96.37,44.27 C24.2 96.39,44.31 96.44,44.36 96.36,44.44 | R31.2 92.45,35.7 | 92.45,35.7 92.43,35.72
I3+  (via drill 0.6)
  Top 0.254: MSP430F47187.14 77.8,56.8 81.5,53.1 109.19,53.1 109.44,52.84
  Top 0.406: 109.44,52.84 109.44,46.16 109.77,45.83 109.77,44.79 109.7,44.72 109.79,44.63 C40.1
  Top 0.61: R63.2 119.6,35.22 119.68,35.29 C36.1 118.83,35.33 118.33,35.83 118.33,42.18 v116.3,44.21 | 109.72,44.51 109.7,44.49 | 109.72,44.51 C40.1 109.75,44.51 109.7,44.46 108.43,44.46 108.17,44.72 v108.17,45.48 | 109.72,44.51 109.77,44.56
  Bottom 0.61: v116.3,44.21 114.27,44.21 112.24,46.24 108.94,46.24 v108.17,45.48
I3-
  Top 0.254: MSP430F47187.15 78.3,57.07 81.76,53.61 109.7,53.61 110.46,52.84
  Top 0.406: 110.46,52.84 110.46,47 111.48,45.99 111.48,44.72 111.49,44.7 C40.2
  Top 0.61: R64.2 107.64,35.24 107.77,35.37 107.74,35.39 C37.1 107.78,35.41 107.79,35.39 107.82,35.42 108.76,35.42 109.19,35.85 109.19,41.16 111.42,43.4 111.53,43.4 111.53,44.28 111.49,44.32 C40.2 | 111.48,44.77 111.49,44.76 C40.2 | 111.58,44.54 111.55,44.51 C40.2
IN+  (via drill 0.6)
  Top 0.254: 123.67,44.21 123.55,44.1 C41.1 | MSP430F47187.16 78.8,57.33 82.01,54.11 115.29,54.11 116.05,53.35
  Top 0.406: 123.67,44.21 123.67,45.73 116.05,53.35
  Top 0.61: C41.1 123.46,43.95 123.41,44.01 123.36,43.95 | 123.54,44.11 123.55,44.09 C41.1 | C41.1 122.65,43.95 v121.89,43.19 | R62.2 133.52,34.89 133.73,35.09 C38.1 134.88,36.37 135.61,37.1 135.61,41.92 v135.1,42.43
  Bottom 0.61: v135.1,42.43 135.1,42.68 133.57,44.21 122.91,44.21 v121.89,43.19
IN-
  Top 0.254: 115.54,54.62 82.27,54.62 79.3,57.59 MSP430F47187.17 | 125.45,44.21 125.25,44.02
  Top 0.406: C41.2 125.25,43.82 | 125.27,43.8 125.27,42.48 | 125.45,44.21 125.19,44.46 125.19,45.22 115.79,54.62 115.54,54.62
  Top 0.61: R65.2 122.35,35.14 122.27,35.22 C39.1 123.17,35.33 123.67,35.83 123.67,40.88 125.27,42.48 | 125.25,43.82 125.27,43.8 | 125.27,44.03 125.25,44.02 C41.2
IS1+
  Top 0.61: 85.69,20.66 85.69,20.74 | 85.26,25.74 TVS1.C | 89.58,25.71 89.57,25.71 L5.1 | TVS1.C 89.58,25.71 | 89.58,25.71 89.81,25.95 | D1.A 84.58,34.79 84.55,34.81 D2.C 84.6,32.98 84.81,32.78 85.06,33.03 85.57,33.03 86.08,32.52 86.08,27.65 85.26,26.83 85.26,25.97 85.31,25.92 85.26,25.87 TVS1.C
  Top 1.27: X4.2 X4.2A 87.39,18.96 85.69,20.66 | 85.69,20.74 85.26,21.17 85.26,25.74
IS2+
  Top 0.61: 98.67,34.66 D5.A 99.36,32.85 D6.C 100.86,32.73 101.57,32.02 101.57,30.75 103.09,29.22 103.09,26.1 103.1,26.1 103.1,25.88 | 104.72,25.79 L7.1 104.82,25.9 103.1,25.88 | 103.1,25.88 102.48,25.87 TVS2.C 100.93,25.87 100.78,25.72 101.09,25.41
  Top 0.813: TVS2.C 101,25.47 101.06,25.41 100.66,25.01
  Top 1.27: X5.2 X5.2A 100.66,25.01
IT2  (via drill 0.5)
  Top 0.406: 22.07,86.37 22.22,86.22 BZ2.P$1 | 22.07,86.37 22.07,87.39 23.25,88.57 R34.2 23.25,91.36 23.34,91.45 23.26,91.53 Q8.3 | U$3.1 2.26,68.59 v2.26,66.81 | 22.07,86.37 20.54,86.37 PLCV2.1
  Bottom 0.61: v2.26,66.81 2.51,66.81 11.15,75.45 18.51,75.45 19.27,76.47 PLCV2.1
L1  (via drill 0.5)
  Top 0.406: 4.54,76.21 4.54,76.47 4.29,76.72 4.29,79.51 5.35,80.58 BZ1.P$2 6.04,81.02 6.07,81.04 6.07,82.05 7.25,83.24 R33.1 | BZ2.P$2 26.49,85.71 26.39,85.61 26.47,85.52 R43.2 32.39,85.52 33.24,86.37 34.51,86.37 34.52,86.37 BZ4.P$2 34.77,86.37 v39.85,86.37 | R35.1 27.49,95.43 28.42,94.5 | BZ3.P$2 29.76,94.43 29.69,94.5 28.42,94.5 | 28.42,94.5 27.91,93.99 27.91,90.44 26.89,89.42 R34.1 24.95,88.82 26.39,87.39 26.39,86.12 26.46,86.05 BZ2.P$2 | PLCGND.1 -L1.1 55.6,92.72 54.18,94.14 U$14.1 | R33.1 7.08,84.59 6.92,84.76 R48.1 | R33.1 7.25,85.27 7.84,85.86 9.88,85.86 11.65,84.09 16.99,84.09 17.5,83.83 25.29,83.83 26.47,84.51 26.47,85.78 26.39,85.86 26.49,85.96 BZ2.P$2
  Top 0.813: U$1.4 4.35,50.87 4.8,51.32 4.8,63.26 4.03,64.02 2.51,64.02 2.45,64.08 U$2.4 4.35,64.08 5.05,64.78 5.05,75.7 4.54,76.21 2.51,76.21 2.45,76.27 U$3.4
  Bottom 0.406: PLCGND.1 40.86,90.94 39.85,89.93 v39.85,86.37
L2  (via drill 0.5)
  Top 0.254: Q9.3 23.26,93.41 23.41,93.41 24.86,91.96 v26.89,91.96
  Top 0.406: U$14.2 57.83,94.7 57.88,94.75 57.88,91.71 58.39,91.2 -L2.1 58.39,90.69 56.61,88.91 39.34,88.91 35.61,93.15 Q11.3 34.56,93.03 34.51,92.98 34.54,92.95 BZ4.P$1 34.54,90.66 34.51,90.69 29.69,90.69 C26.2 29.69,91.71 v28.93,92.47 | Q5.3 14.07,87.25 v14.19,87.13 | v15.97,88.4 18.26,88.4 23.26,93.41
  Bottom 0.406: v28.93,92.47 27.4,92.47 v26.89,91.96 | v14.19,87.13 14.19,87.39 15.21,88.4 v15.97,88.4
LED_A
  Top 0.254: LED1.A 92.43,121.93 LED_EN.2
LED_B
  Top 0.254: LED_EN.4 90.65,117.36 93.35,120.06 LED2.A
LED_C  (via drill 0.5, 0.6)
  Top 0.254: v88.01,69.68 88.01,69.71 87.62,70.1 MSP430F47187.43 | 96.3,117.93 LED3.A 95.98,118.12 95.98,116.85 97,115.84 v101.32,115.84
  Bottom 0.254: v88.01,69.68 88.01,68.03 88.06,67.98 | 88.06,67.98 89.25,66.79 | v101.32,115.84 101.57,115.84 102.08,115.33 108.68,115.33 109.85,114.16 109.85,89.19 108.02,87.24 103.7,87.24 100.81,84.34 100.81,66.31 100.55,66.05 90,66.05 88.07,67.98 88.06,67.98 | 88.06,67.98
MSP430_DVCC  (via drill 0.6, 0.9)
  Top 0.254: MSP430F47187.64 76.8,76.59 77.69,77.48 77.69,80.48 78.96,81.04 78.96,82.11 79.07,82.21 78.99,82.28 C8.+ 79.12,82.41 79.22,82.31 79.74,82.83 C9.2 | MSP430F47187.92 67.48,65.6 65.25,67.83 65.25,70.09 64.13,71.21 64.13,72.05 64.23,72.15 C2.+
  Top 0.406: C2.+ 63.72,72.15 63.56,72.31 C4.2
  Top 0.813: 64.87,77 64.87,77.86 | 64.87,77 v64.87,76.92 | C4.2 63.56,75.28 64.87,77 | v80.23,81.11 80.39,81.29 81,81.9 81,82.64 80.97,82.66 81,82.69 C9.2 | v75.41,51.83 74.86,51.28 R7.1 74.86,46.97 74.9,47 v74.9,44.46
  Bottom 0.813: v71.85,63.26 68.55,59.7 68.55,54.11 v75.41,51.83 | v71.85,63.26 71.85,64.78 v71.6,65.04 | v71.85,63.26 v73.38,63.26 | J5.2 58.39,60.97 v74.9,44.46
  other vias: 64.87,77.97
  pour VCC: 59.66,63 59.48,93.43 90.65,93.48 90.62,62.65 59.66,62.6
N$1
  Top 0.406: 23.92,76.52 23.92,76.29 23.08,75.45 19.02,75.45 D27.A | 23.92,76.52 D9.A | C53.1 27.74,75.87 27.4,76.21 24.23,76.21 23.92,76.52
  Top 0.61: ISO3.2 35.87,72.06 35.78,72.15 35.87,72.24 35.87,73.2 35.24,73.84 R124.1 30.54,73.84 30.45,73.93 29.43,73.93 28.67,74.69 C53.1
N$2
  Top 0.254: RF1.7 112.97,153.2 113.25,152.92 R30.2
N$3
  Top 0.813: U$1.3 2.51,48.02 2.2,47.71 U$1.2
N$4
  Top 0.254: 98.05,121.71 98.01,121.68 | LED1.C 98.05,121.71 | R1.2 98.27,121.93 98.05,121.71
N$5
  Top 0.813: U$1.8 14.64,43.25 14.7,43.19 14.45,42.94 | 2.51,28.97 C58.1 2.76,28.97 14.45,40.65 14.45,43.19 14.39,43.25 U$1.8 | U$1.8 14.13,43.25 13.94,43.45 13.69,43.19
N$6
  Top 0.254: TP8.TP 117.32,155.71 117.29,155.74 RF1.11
N$7
  Top 0.254: LED2.C 98.11,120.06 98.27,119.9 98.41,120.04 R2.2
N$8
  Top 0.406: R13.2 38.12,37.15 38.07,37.1 38.12,37.05 R12.1
N$9
  Top 0.254: D14.C 123.16,72.91
  Top 0.406: U3.2 121.25,74.05 121.89,73.42 122.65,73.42 123.16,72.91 | 123.16,71.13 R45.2 D14.C
N$10  (via drill 0.9)
  Top 0.813: U$3.8 14.25,68.65 14.19,68.59 v10.38,68.59
  Bottom 1.27: C60.1 10.82,17.86 10.38,18.3 v10.38,68.59
N$11
  Top 0.813: U$3.3 2.45,73.73 2.51,73.67 2.2,73.36 U$3.2
N$12  (via drill 0.5)
  Top 0.406: Q10.3 34.55,97.52 34.51,97.55 34.56,97.6 34.56,100.85 34.51,100.85 34.26,101.1 32.74,101.1 32.48,100.85 32.48,99.58 31.6,98.7 BZ3.P$1 | R35.2 26.98,97.13 28.42,98.56 29.69,98.56 29.82,98.7 BZ3.P$1 | v28.61,96.2 28.61,96.46 29.94,97.8 29.94,98.82 29.95,98.81 BZ3.P$1 | 2.26,56.4 2.26,54.11 PLCV3.1
  Top 0.813: 2.26,56.4 U$2.1
  Bottom 0.406: v28.61,96.2 25.62,93.23 25.62,81.29 16.73,72.4 11.91,72.4 8.86,69.35 8.86,58.18 4.03,53.35 2.51,53.35 PLCV3.1
N$13
  Top 0.406: 43.91,43.19 43.99,43.12 | R13.1 41.51,39.01 43.91,41.41 43.91,43.19 | 43.91,43.19 43.95,43.23 R14.2
N$14
  Top 0.406: R15.2 R14.1 40.01,44.93 39.92,45.02 39.83,44.93 R16.1
N$15
  Top 0.406: R20.2 57.91,42.96 57.88,42.94 57.96,42.86 R19.1
N$16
